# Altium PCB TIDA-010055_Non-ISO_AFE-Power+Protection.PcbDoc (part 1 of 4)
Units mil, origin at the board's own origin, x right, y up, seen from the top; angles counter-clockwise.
Board outline 3622.05 x 4330.71 mil, 4 copper layers (Top Layer, GND Layer, PWR Layer, Bottom Layer), stack 63.6 mil thick; 398 components, 177 nets, 1104 pads, 428 vias.
Unrouted connection lines stored in the file: 1.
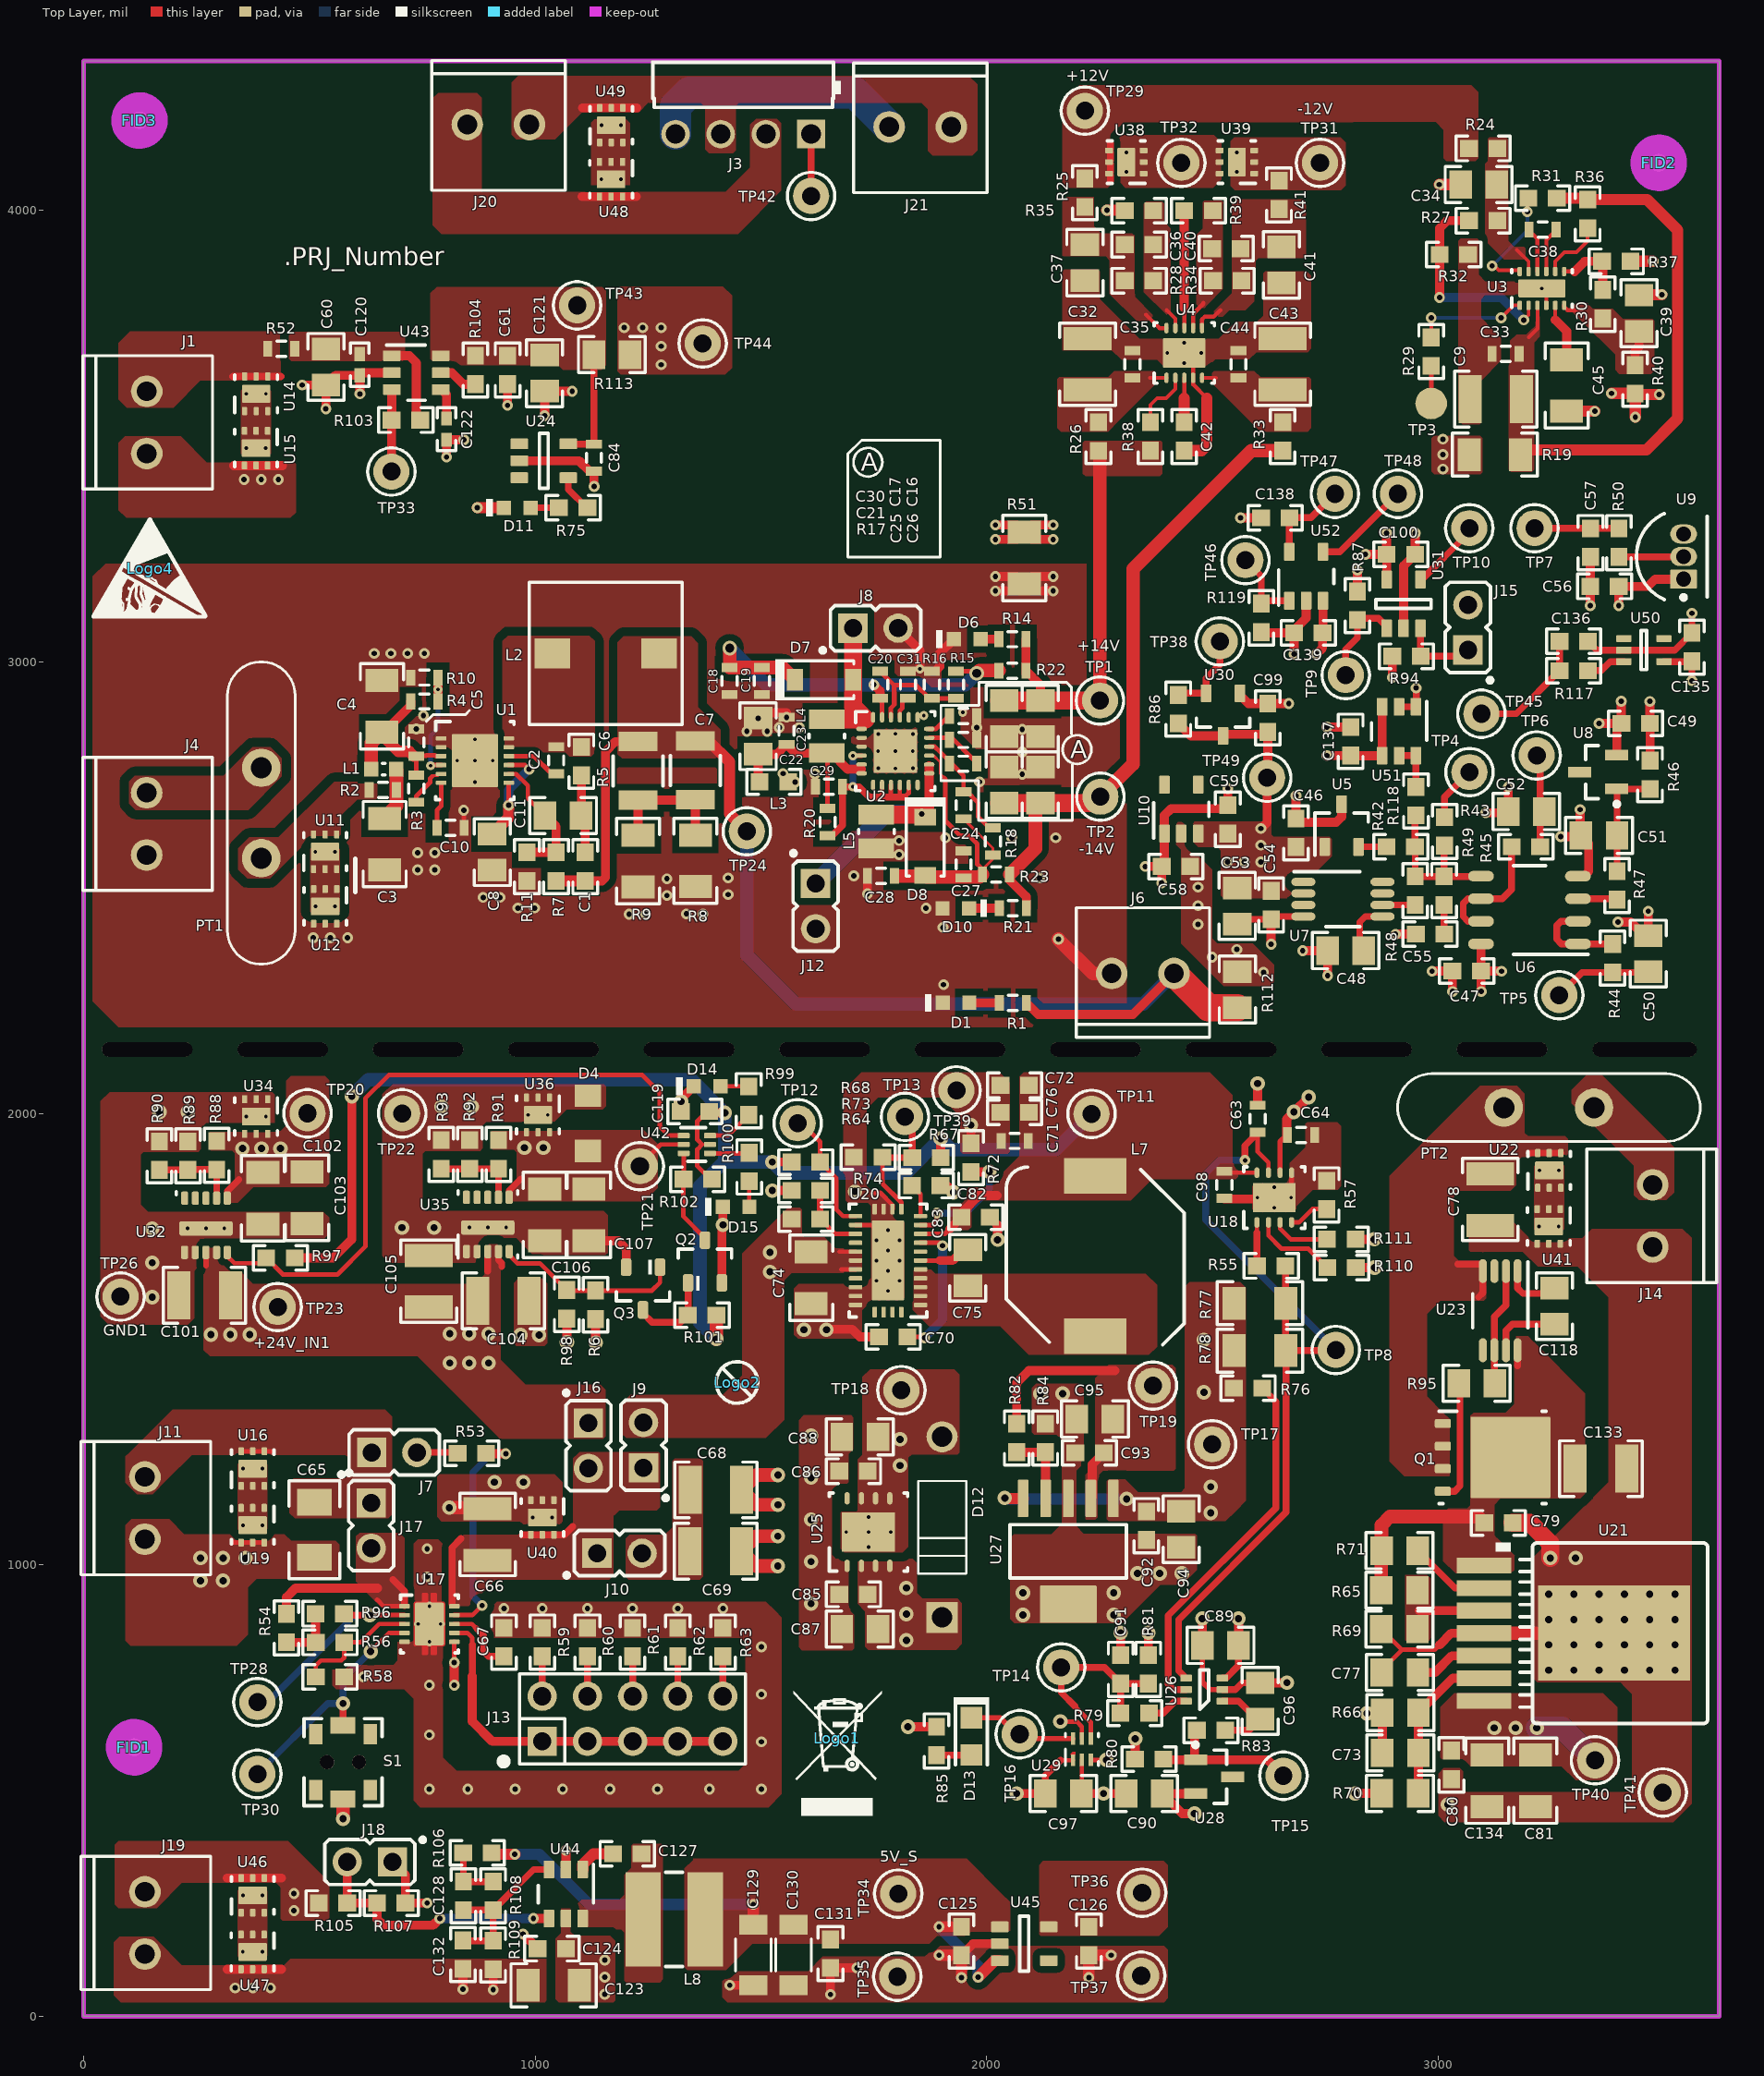
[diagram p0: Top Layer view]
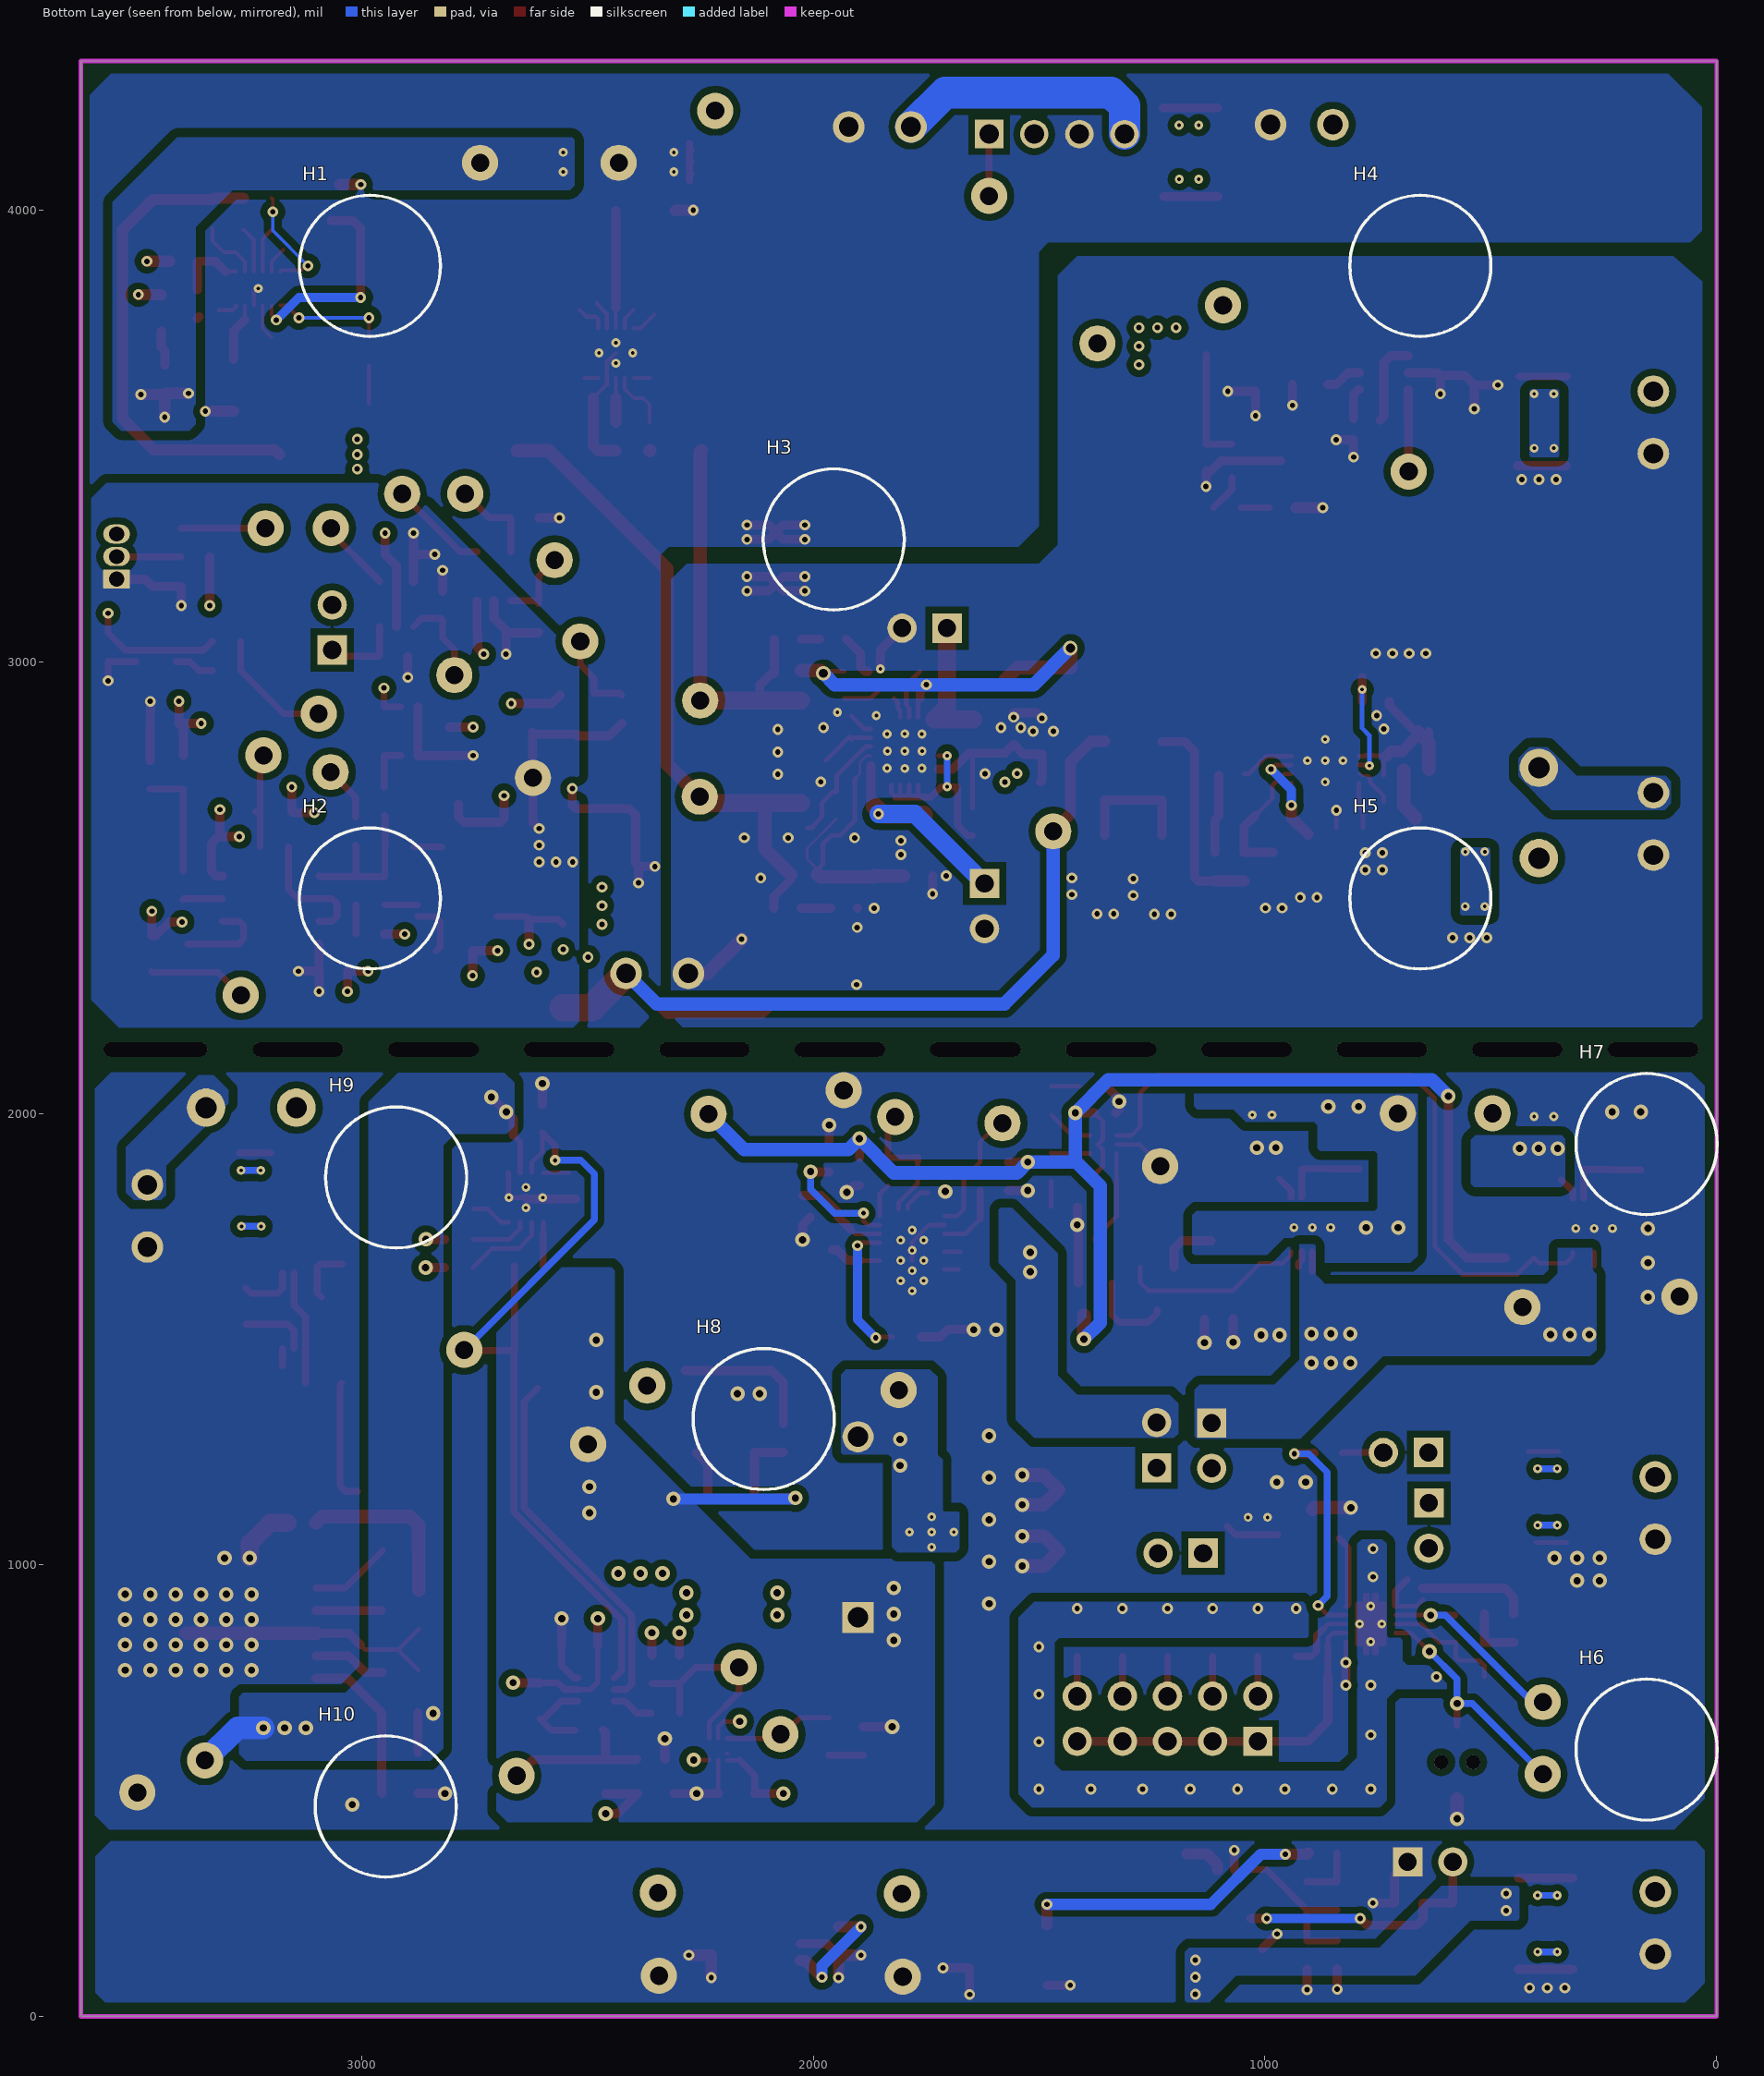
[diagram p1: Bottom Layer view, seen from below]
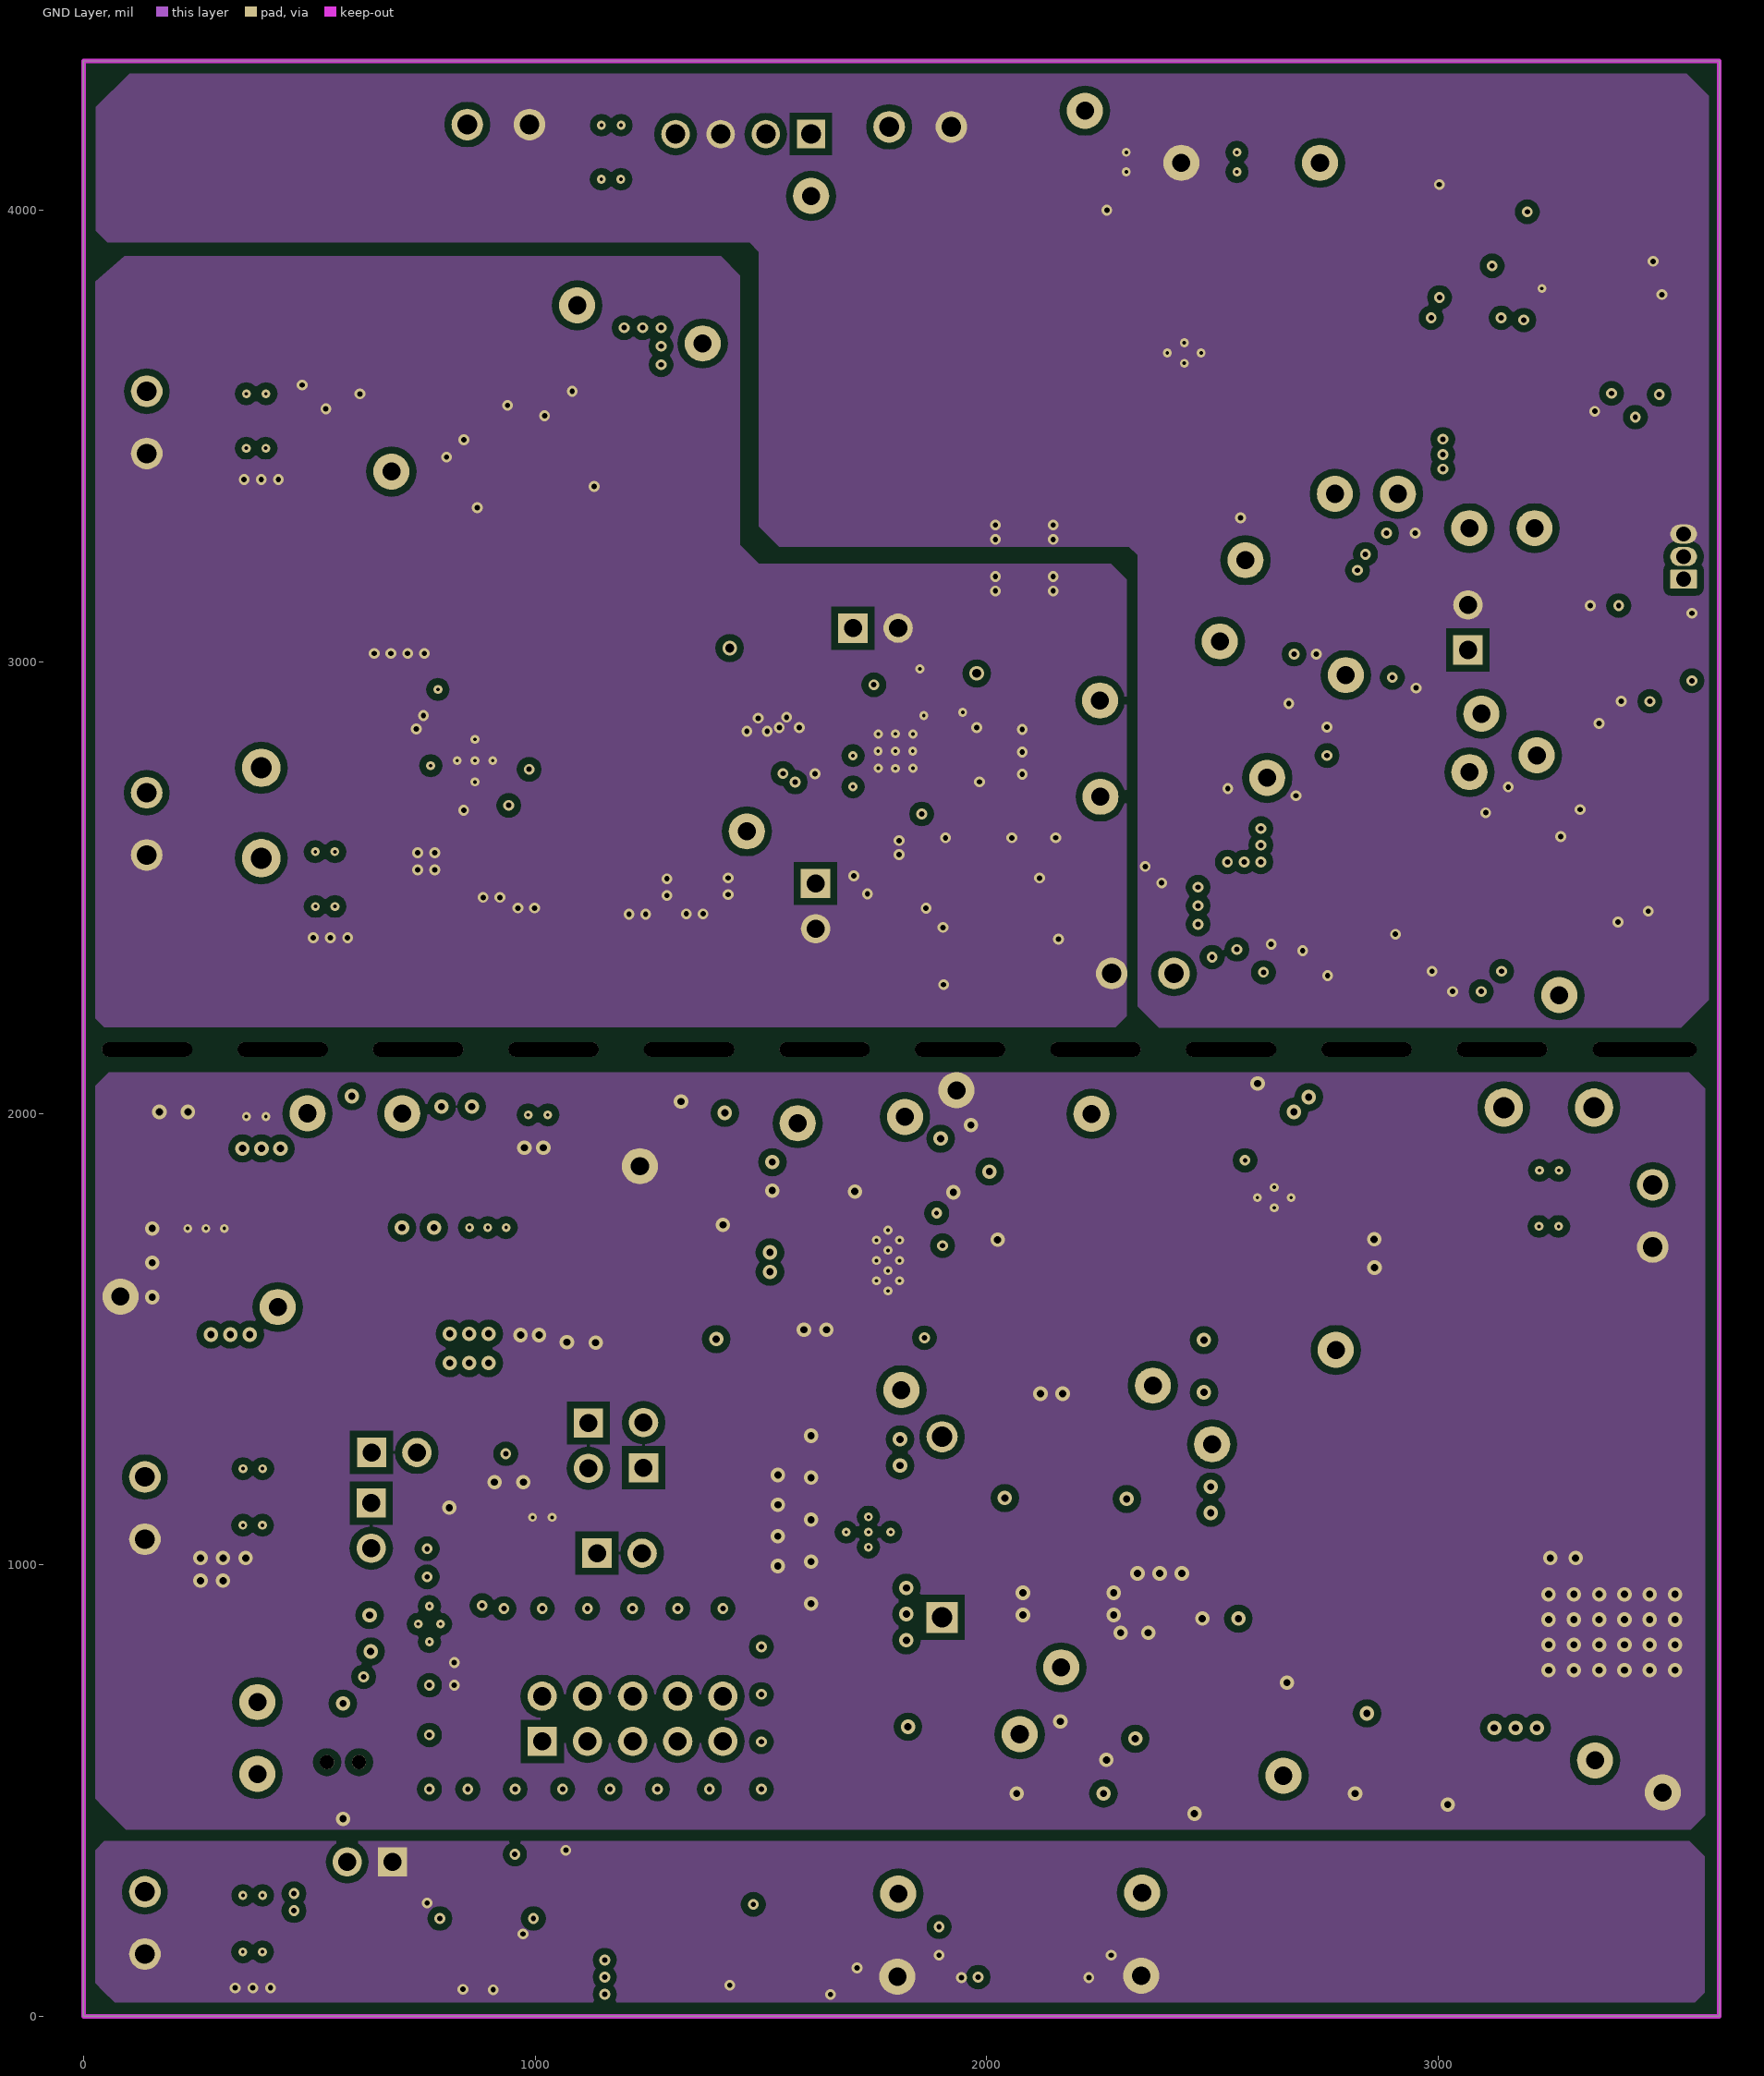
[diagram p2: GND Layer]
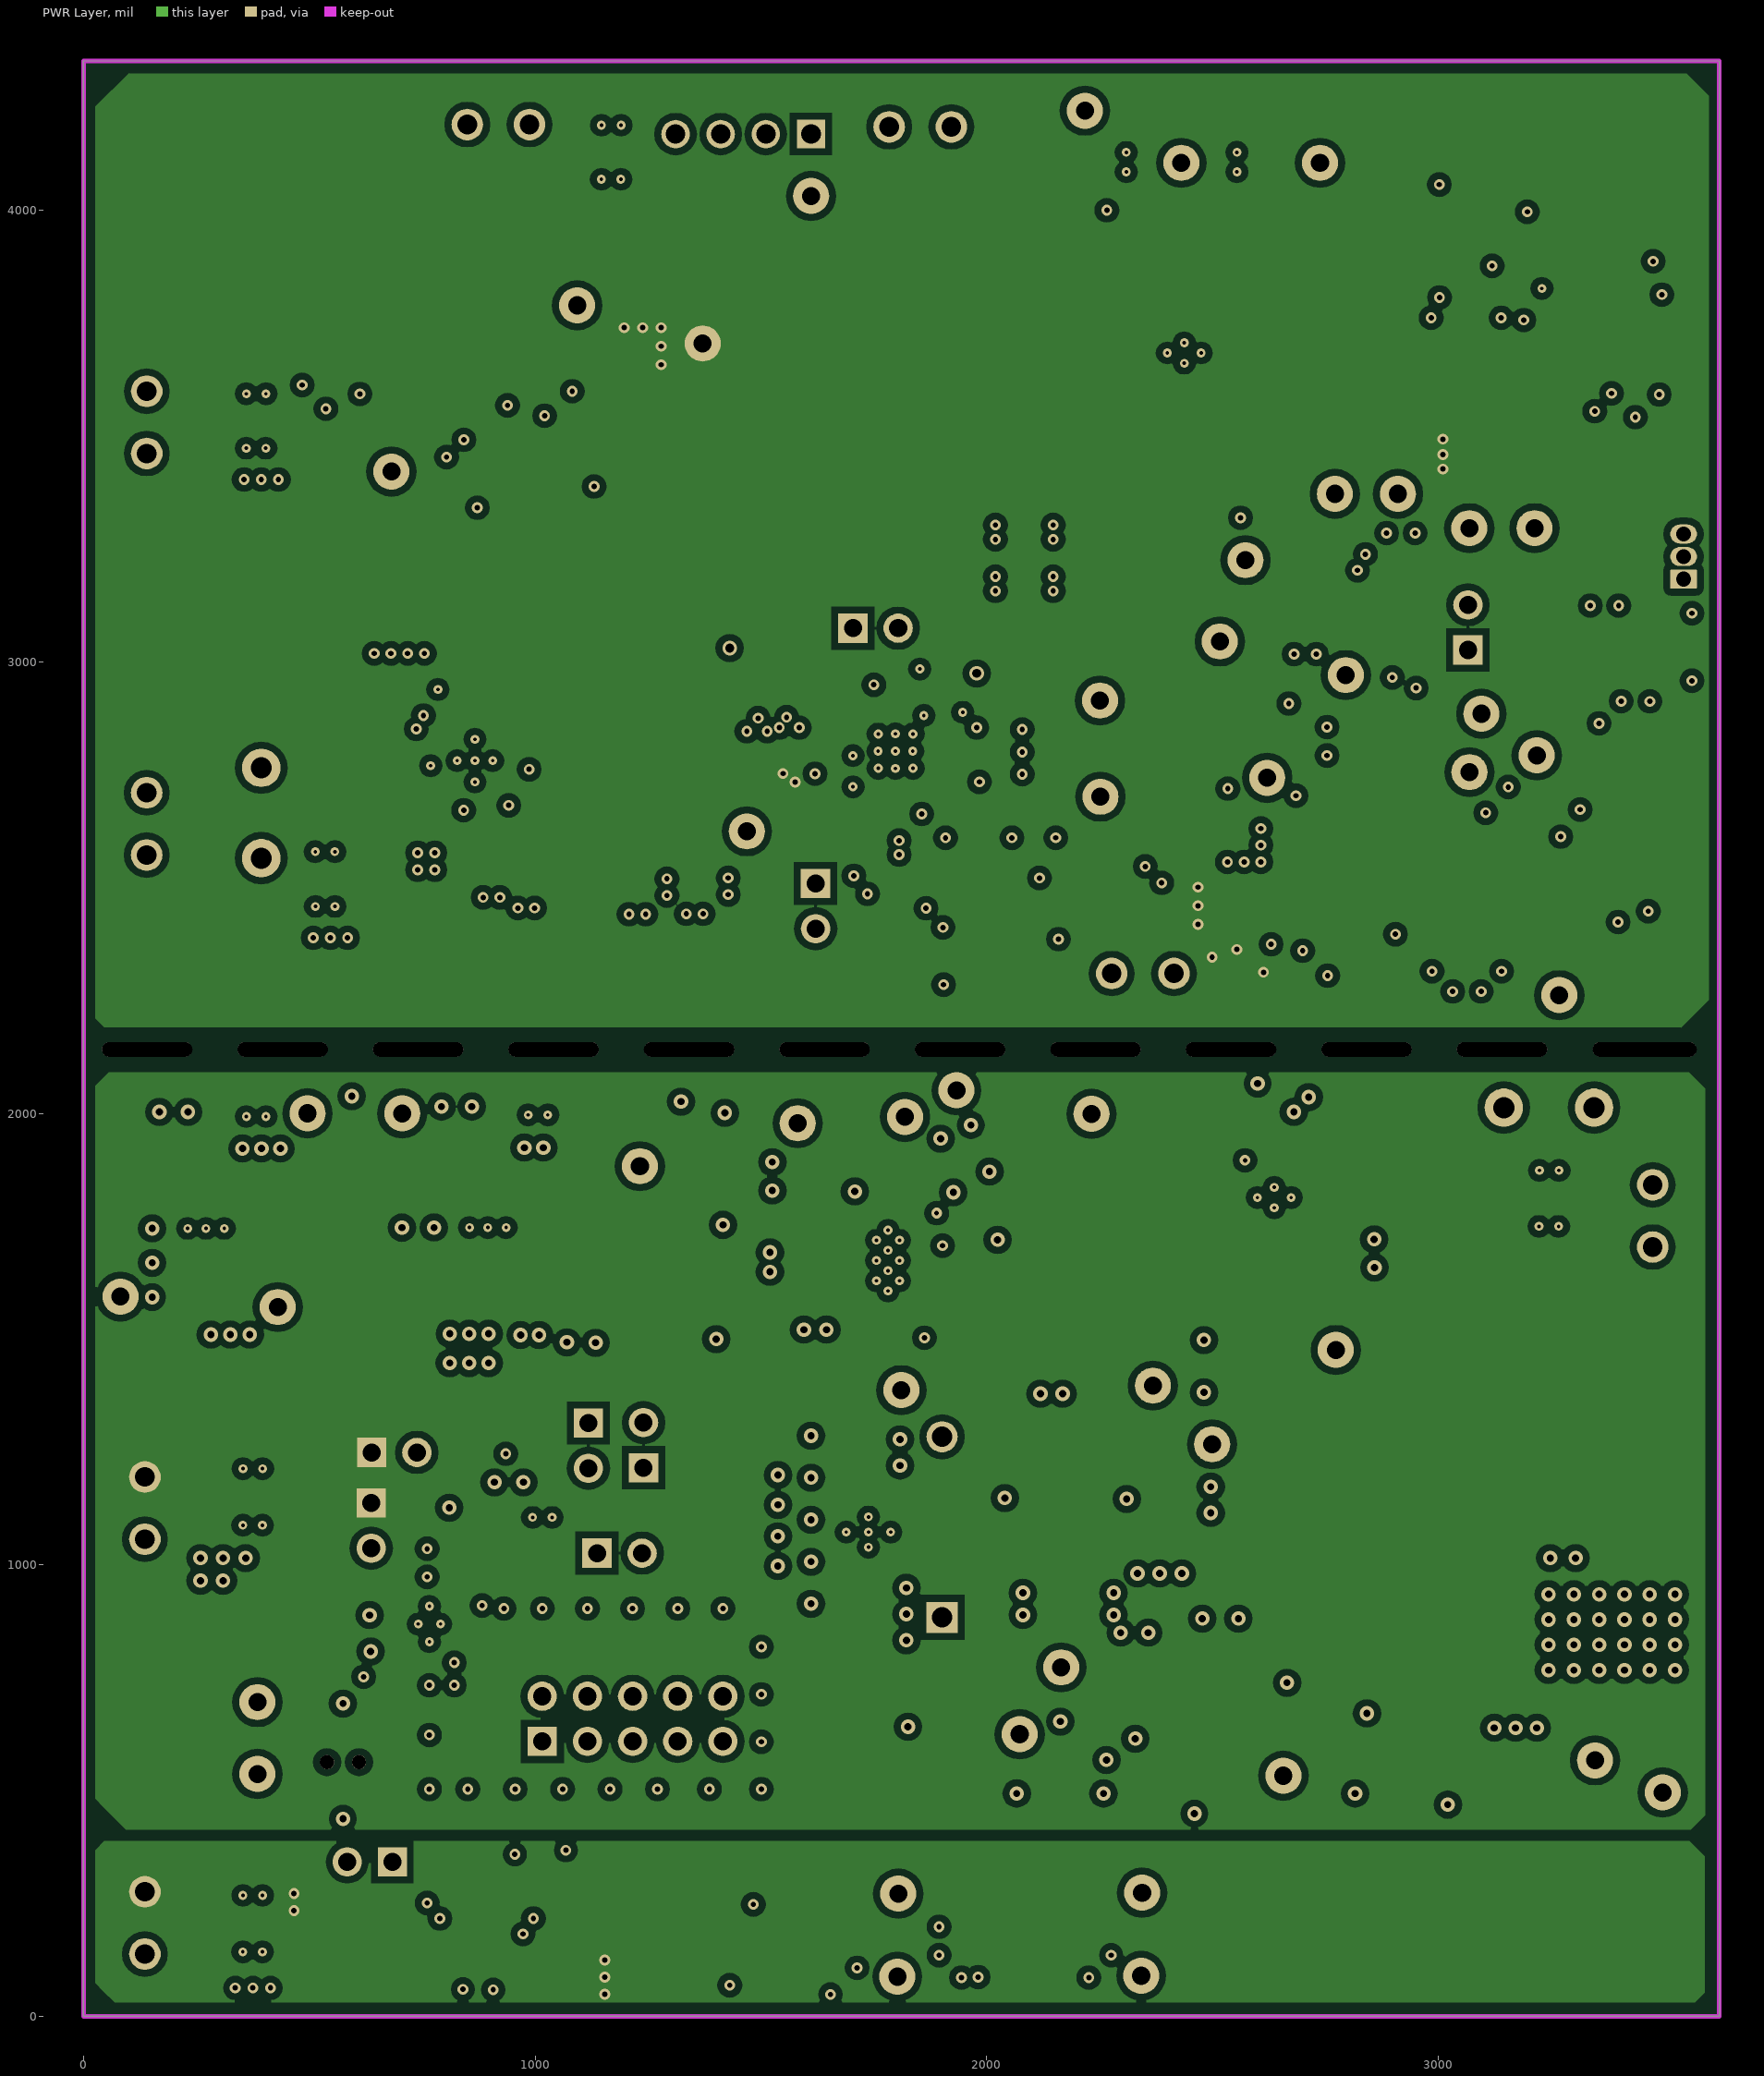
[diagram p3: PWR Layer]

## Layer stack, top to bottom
Top Solder: solder mask 0.3, Solder Resist, Dk 3.5
Top Layer: signal copper 1.4
Dielectric1: core 15, FR-4 High Tg, Dk 4.5
GND Layer: signal copper 1.4
Dielectric 2: prepreg 28, FR-4 High Tg, Dk 4.5
PWR Layer: signal copper 1.4
Dielectric 3: core 15, FR-4 High Tg, Dk 4.5
Bottom Layer: signal copper 1.4
Bottom Solder: solder mask 0.3, Solder Resist, Dk 3.5

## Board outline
0,0 0,4330.71 3622.05,4330.64 3622.05,0

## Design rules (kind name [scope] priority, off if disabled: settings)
AcuteAngle [All] p1: minimum=4.50000000000000E+0001 checktracksonly=FALSE
AssemblyTestPointUsage [All] p1: valid=2
BoardOutlineClearance BoardOutlineClearance_MountingHoles [OnCopper and InComponentClass('Mounting Holes')] p1: gap=30 ignorepadtopadclearanceinfootprint=FALSE
BoardOutlineClearance BoardOutlineClearance_Poly [OnCopper and InPoly] p2: gap=25 ignorepadtopadclearanceinfootprint=FALSE
BoardOutlineClearance [OnCopper and Not InComponentClass('Logo') and not InComponentClass('FiducialMark') and not InRegion(1000,500,4000,800)] p3: gap=15 ignorepadtopadclearanceinfootprint=FALSE
Clearance Clearance_Poly_poly [InPoly vs InPoly] p1: gap=20 ignorepadtopadclearanceinfootprint=FALSE except(0: Arc-Hole Track-Hole SMDPad-Hole THPad-Hole Via-Hole Fill-Hole Poly-Hole Region-Hole Text-Hole)
Clearance Clearance_Keepouts [((IsTrack Or IsArc) And Not InPoly) And IsFree and IsKeepOut vs ((IsTrack Or IsArc) And Not InPoly) And IsFree and IsKeepOut] p2: gap=20 ignorepadtopadclearanceinfootprint=FALSE except(0: Arc-Hole Track-Hole SMDPad-Hole THPad-Hole Via-Hole Fill-Hole Poly-Hole Region-Hole Text-Hole)
Clearance Clearance_Poly [InPolygon] p3: gap=15 ignorepadtopadclearanceinfootprint=FALSE except(0: Arc-Hole Track-Hole SMDPad-Hole THPad-Hole Via-Hole Fill-Hole Poly-Hole Region-Hole Text-Hole)
Clearance [All] p4: gap=7.87 ignorepadtopadclearanceinfootprint=FALSE except(0: Arc-SMDPad Arc-THPad Arc-Hole Track-Hole SMDPad-Hole THPad-Hole Via-Hole Fill-Hole Poly-Hole Region-Hole Text-Hole)
ComponentClearance ComponentClearance_MountingHoles_FiducialMarks [InComponentClass('Mounting Holes') vs InComponentClass('FiducialMark')] p1: gap=10 collisioncheckmode=3 verticalgap=10 showdistances=FALSE
ComponentClearance ComponentClearance_Shunt [InComponentClass('Header') vs InComponentClass('Shunt')] p2: gap=0 collisioncheckmode=3 verticalgap=0 showdistances=FALSE
ComponentClearance ComponentClearance_Logo [InComponentClass('Logo')] p3: gap=5 collisioncheckmode=3 verticalgap=5 showdistances=FALSE
ComponentClearance ComponentClearance_ScrewToNut [(HasFootprint('NY PMS 440 0025 PH')) vs (HasFootprint('Keystone_1902C'))] p4: gap=5 collisioncheckmode=3 verticalgap=10 showdistances=FALSE
ComponentClearance ComponentClearance_MountingHoles [InComponentClass('Mounting Holes')] p5: gap=250 collisioncheckmode=3 verticalgap=100000 showdistances=FALSE
ComponentClearance ComponentClearance_SmallPassives [HasFootprint('0201*') or HasFootprint('0402*') or HasFootprint('0508') or HasFootprint('0603*') or HasFootprint('0612') or HasFootprint('0805*') or HasFootprint('0815*') or HasFootprint('0830*') or HasFootprint('1206*') or HasFootprint('1210*') or HasFootprint('1808*') or HasFootprint('1812*') or HasFootprint('1825*') or HasFootprint('2010*') or HasFootprint('2220*') or HasFootprint('2225*') or HasFootprint('2512*') or HasFootprint('2728*') or HasFootprint('3518*') vs HasFootprint('0201*') or HasFootprint('0402*') or HasFootprint('0508') or HasFootprint('0603*') or HasFootprint('0612') or HasFootprint('0805*') or HasFootprint('0815*') or HasFootprint('0830*') or HasFootprint('1206*') or HasFootprint('1210*') or HasFootprint('1808*') or HasFootprint('1812*') or HasFootprint('1825*') or HasFootprint('2010*') or HasFootprint('2220*') or HasFootprint('2225*') or HasFootprint('2512*') or HasFootprint('2728*') or HasFootprint('3518*')] p6: gap=5 collisioncheckmode=3 verticalgap=5 showdistances=FALSE
ComponentClearance ComponentClearance_THtoSMT [IsThruComponent vs IsSMTComponent] p7: gap=5 collisioncheckmode=3 verticalgap=5 showdistances=FALSE
ComponentClearance ComponentClearance_THtoTH [IsThruComponent vs IsThruComponent] p8: gap=0 collisioncheckmode=3 verticalgap=10 showdistances=FALSE
ComponentClearance [All] p9: gap=10 collisioncheckmode=3 verticalgap=10 showdistances=FALSE
DiffPairsRouting [All] p1: maxlimit=100 minlimit=10 mostfreqgap=10 toplayer_minwidth=15 toplayer_maxwidth=15 toplayer_prefwidth=15 midlayer1_minwidth=15 midlayer1_maxwidth=15 midlayer1_prefwidth=15 midlayer2_minwidth=15 midlayer2_maxwidth=15 midlayer2_prefwidth=15 bottomlayer_minwidth=15 bottomlayer_maxwidth=15 bottomlayer_prefwidth=15 maxuncoupledlength=1000
FabricationTestPointUsage TestPointUsage [All] p1: valid=2 allowmultiple=FALSE
FabricationTestpoint Testpoint [All] p1: side=3 testpointundercomponent=TRUE minsize=40 maxsize=100 preferedsize=60 minholesize=0 maxholesize=40 preferedholesize=32 testpointgrid=1 allowsidetop=TRUE allowsidebottom=TRUE usegrid=TRUE gridtolerance=0.01
FanoutControl Fanout_LCC [IsLCC] p1: bgadir=Out bgaviamode=Centered fanoutstyle=Auto fanoutdirection=Alternating viagrid=1 // Fanout_LCC (Default Rule)
FanoutControl Fanout_BGA [IsBGA] p2: bgadir=Out bgaviamode=Centered fanoutstyle=Auto fanoutdirection=Alternating viagrid=1 // Fanout_BGA (Default Rule)
FanoutControl Fanout_Default [All] p4: bgadir=Out bgaviamode=Centered fanoutstyle=Auto fanoutdirection=Alternating viagrid=1 // Fanout_Default (Default Rule)
FanoutControl Fanout_Small [(CompPinCount < 5)] p5: bgadir=Out bgaviamode=Centered fanoutstyle=Auto fanoutdirection=OutThenIn viagrid=1 // Fanout_Small (Default Rule)
HoleSize [All] p1: absolutevalues=TRUE maxlimit=251 minlimit=7.87 maxpercent=80.000 minpercent=20.000
MinimumAnnularRing MinimumAnnularRing_ThermalPadVias [IsVia and InAnyComponent] p1: minimumring=4
MinimumAnnularRing [All] p2: minimumring=4
MinimumSolderMaskSliver MinimumSolderMaskSliver_Logo [InComponentClass('Logo') vs InComponentClass('Logo')] p1: minsoldermaskwidth=0.7
MinimumSolderMaskSliver [All] p2: minsoldermaskwidth=3.94
PlaneClearance [All] p1: clearance=10
PlaneConnect [All] p1: planeconnectstyle=Relief reliefexpansion=10 reliefentries=4 reliefconductorwidth=10 reliefairgap=10
PolygonConnect PolygonConnectThermalVia [isvia] p1: connectstyle=Direct reliefconductorwidth=10 reliefentries=4 polygonreliefangle="90 Angle" airgapwidth=10
PolygonConnect PolygonConnectThermalPad [((ObjectKind = 'Pad') And (((Name Like 'U*') or (Name Like 'D*')) and (InComponentClass('TIDA-00183_pg-4_Driver') or InComponentClass('TIDA-00183_pg-5_OP_Connector')))) or ((ObjectKind = 'Pad') And (Name like 'U61*'))] p2: connectstyle=Direct reliefconductorwidth=10 reliefentries=4 polygonreliefangle="90 Angle" airgapwidth=10
PolygonConnect [All] p3: connectstyle=Direct reliefconductorwidth=10 reliefentries=4 polygonreliefangle="90 Angle" airgapwidth=5
RoutingVias ThermalPadVias [IsVia and InAnyComponent] p1: holewidth=7.87 width=19.68 viastyle="Through Hole" minholewidth=7.87 minwidth=19.68 maxholewidth=12.99 maxwidth=23.62
RoutingVias [All] p2: holewidth=16 width=34 viastyle="Through Hole" minholewidth=8 minwidth=20 maxholewidth=40 maxwidth=65
SilkToBoardRegionClearance [Not ((IsComment or IsDesignator) And (Hide <> 'False')) and not InRegion(1000,500,4000,800)] p1:
SilkToSilkClearance SilkToSilkClearance_Pb-FreeLogo [(HasFootprint('Pb-Free_Overlay_Medium') OR HasFootprint('Pb-Free_Overlay_Small')) vs (HasFootprint('Pb-Free_Overlay_Medium') OR HasFootprint('Pb-Free_Overlay_Small'))] p1: silktosilkclearance=0
SilkToSilkClearance [All] p2: silktosilkclearance=4
SilkToSolderMaskClearance SilkToComponentPadClearance [IsPad and InAnycomponent] p1: minsilkscreentomaskgap=5 clearancetoexposedcopper=TRUE
SilkToSolderMaskClearance "Silk to Solder Mask Opening" [All] p2: minsilkscreentomaskgap=4 clearancetoexposedcopper=FALSE
SolderMaskExpansion [All] p1: expansion=1.97
Width [All] p1: maxlimit=100 minlimit=6 preferedwidth=10 checkconnectedcopper=TRUE
14 further rules are at their usual default settings.

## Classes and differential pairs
component class "TIDA-010055_Non-ISO_AFE-Power+Protection _Pg3": C1 C2 C3 C4 C5 C6 C7 C8 C10 C11 C60 C61 C84 C120 C121 C122 D1 D11 J1 J4 J6 L1 L2 PT1 R1 R2 R3 R4 R5 R7 R8 R9 R10 R11 R52 R75 R103 R104 R112 R113 TP24 TP33 TP43 TP44 U1 U11 U12 U14 U15 U24 U43
component class "TIDA-010055_Non-ISO_AFE-Power+Protection _Pg8": C123 C124 C125 C126 C127 C128 C129 C130 C131 C132 J3 J18 J19 J20 J21 L8 R105 R106 R107 R108 R109 TP34 TP35 TP36 TP37 TP42 U44 U45 U46 U47 U48 U49
component class "TIDA-010055_Non-ISO_AFE-Power+Protection _Pg7": C63 C64 C73 C77 C78 C79 C80 C81 C85 C86 C87 C88 C89 C90 C91 C92 C93 C94 C95 C96 C97 C98 C118 C133 C134 D12 D13 J14 PT2 Q1 R55 R57 R65 R66 R69 R70 R71 R76 R77 R78 R79 R80 R81 R82 R83 R84 R85 R95 R110 R111 TP8 TP14 TP15 TP16 TP17 TP18 TP19 TP40 TP41 U18 U21 U22 U23 U25 U26 U27 U28 U29 U41
component class "TIDA-010055_Non-ISO_AFE-Power+Protection _Pg5": C9 C32 C33 C34 C35 C36 C37 C38 C39 C40 C41 C42 C43 C44 C45 C46 C47 C48 C49 C50 C51 C52 C53 C54 C55 C56 C57 C58 C59 C99 C100 C135 C136 C137 C138 C139 J15 R19 R24 R25 R26 R27 R28 R29 R30 R31 R32 R33 R34 R35 R36 R37 R38 R39 R40 R41 R42 R43 R44 R45 R46 R47 R48 R49 R50 R51 R86 R87 R94 R117 R118 R119 TP3 TP4 TP5 TP6 TP7 TP9 TP10 TP29 TP31 TP32 TP38 TP45 TP46 TP47 TP48 TP49 U3 U4 U5 U6 U7 U8 U9 U10 U30 U31 U38 U39 U50 U51 U52
component class Header: J3 J7 J8 J9 J10 J12 J13 J15 J16 J17 J18
component class AssemblyNote: ZZ1 ZZ2 ZZ3 ZZ4
component class FiducialMark: FID1 FID2 FID3
component class "TIDA-010055_Non-ISO_AFE-Power+Protection _EVM_Hardware_Pg9": FID1 FID2 FID3 H1 H2 H3 H4 H5 H6 H7 H8 H9 H10 Logo1 Logo2 Logo3 Logo4 ZZ1 ZZ2 ZZ3 ZZ4
component class "TIDA-010055_Non-ISO_AFE-Power+Protection _Pg4": C16 C17 C18 C19 C20 C21 C22 C23 C24 C25 C26 C27 C28 C29 C30 C31 D6 D7 D8 D10 J8 J12 L3 L4 L5 R14 R15 R16 R17 R18 R20 R21 R22 R23 TP1 TP2 U2
component class "TIDA-010055_Non-ISO_AFE-Power+Protection _Pg6": C65 C66 C67 C68 C69 C70 C71 C72 C74 C75 C76 C82 C83 C101 C102 C103 C104 C105 C106 C107 C119 D4 D14 D15 J7 J9 J10 J11 J13 J16 J17 L7 Q2 Q3 R6 R53 R54 R56 R58 R59 R60 R61 R62 R63 R64 R67 R68 R72 R73 R74 R88 R89 R90 R91 R92 R93 R96 R97 R98 R99 R100 R101 R102 S1 TP11 TP12 TP13 TP20 TP21 TP22 TP23 TP26 TP28 TP30 TP39 U16 U17 U19 U20 U32 U34 U35 U36 U40 U42

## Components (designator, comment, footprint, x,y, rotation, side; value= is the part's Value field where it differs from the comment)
C1 "06031C472KAT2A" 0603 1110.88,2546.43 r90 top value=4700pF
C2 "CGA3E2X7R1H103K080AA" 0603S 1046.54,2781.94 r90 top value=0.01uF
C3 "UMK316B7225KL-T" 1206 666.73,2596.16 r270 top value=2.2uF
C4 "UMK316B7225KL-T" 1206 660.73,2901.16 r90 top value=2.2uF
C5 "C0603X124K5RAC7867" 0603S 736.73,2821.16 r90 top value=0.1uF
C6 "C1210C107M8PACTU" 1210_280 1227.88,2758.39 r270 top value=100uF
C7 "C1210C107M8PACTU" 1210_280 1354.88,2759.39 r270 top value=100uF
C8 "C0805C104K1RACTU" 0805_HV 904.88,2578.43 r270 top value=0.1uF
C9 "" 1210 3127.11,3581.98 r0 top value=10uF
C10 "885012206034" 0603S 812.73,2632.16 r0 top value=1000pF
C11 "C0805C104K1RACTU" 0805_HV 1061.88,2659.43 r180 top value=0.1uF
C16 "GRM21BC71E106KE11L" 0805_HV 2118.73,2874.16 r270 top value=10uF
C17 "GRM21BC71E106KE11L" 0805_HV 2038.73,2874.16 r270 top value=10uF
C18 "CGA3E1X7R1E105K080AC" 0603S 1430.73,2957.43 r270 top value=1uF
C19 "C0603X124K5RAC7867" 0603S 1501.88,2957.43 r270 top value=0.1uF
C20 "06035A6R8CAT2A" 0603S 1763.73,2949.16 r90 top value=6.8pF
C21 "EMK107B7224KA-T" 0603S 1947.73,2827.16 r0 top value=0.22uF
C22 "GRM21BC71E106KE11L" 0805_HV 1493.73,2835.16 r90 top value=10uF
C23 "C0603X124K5RAC7867" 0603S 1556.73,2847.16 r90 top value=0.1uF
C24 "C0603C569K5GACTU" 0603S 1948.73,2682.16 r270 top value=5.6pF
C25 "GRM21BC71E106KE11L" 0805_HV 2038.73,2727.16 r270 top value=10uF
C26 "GRM21BC71E106KE11L" 0805_HV 2118.73,2727.16 r270 top value=10uF
C27 "CGA3E1X7R1E105K080AC" 0603S 1948.73,2551.16 r270 top value=1uF
C28 "C0603X124K5RAC7867" 0603S 1765.73,2526.16 r0 top value=0.1uF
C29 "C0603X124K5RAC7867" 0603S 1650.73,2723.16 r180 top value=0.1uF
C30 "885012206087" 0603S 1947.73,2880.16 r0 top value=4700pF
C31 "885012206040" 0603S 1825.73,2949.16 r90 top value=0.01uF
C32 "" 1210 2223.4,3658.91 r270 top value=10uF
C33 "CGA3E1X7R1E105K080AC" 0603S 3149.2,3681.98 r180 top value=1uF
C34 "C0805C225K8RACTU" 0805_HV 3089.2,4056.98 r180 top value=2.2uF
C35 "CGA3E1X7R1E105K080AC" 0603S 2322.4,3659 r90 top value=1uF
C36 "885012206040" 0603 2337.4,3923.93 r0 top value=0.01uF
C37 "C0805C225K8RACTU" 0805_HV 2217.4,3884 r270 top value=2.2uF
C38 "CGA3E1X7R1E105K080AC" 0603S 3230.7,3956.98 r180 top value=1uF
C39 "C0805C225K8RACTU" 0805_HV 3444.2,3771.98 r90 top value=2.2uF
C40 "885012206040" 0603 2530.4,3915 r180 top value=0.01uF
C41 "C0805C225K8RACTU" 0805_HV 2652.4,3879 r270 top value=2.2uF
C42 "885012206040" 0603 2437.4,3499 r270 top value=0.01uF
C43 "" 1210 2655.4,3658.91 r270 top value=10uF
C44 "CGA3E1X7R1E105K080AC" 0603S 2557.4,3659 r90 top value=1uF
C45 "C3216X7R1E475M160AC" 1206 3284.2,3611.98 r270 top value=4.7uF
C46 "06033D104KAT2A" 0603 2684.81,2621.23 r90 top value=0.1uF
C47 "06033D104KAT2A" 0603 3062.81,2315.23 r0 top value=0.1uF
C48 "CL21B105KPFNNNE" 0805_HV 2794.81,2360.23 r180 top value=1uF
C49 "06033D104KAT2A" 0603 3436.85,2863.72 r0 top value=0.1uF
C50 "C2012X7R1H105K125AE" 0805_HV 3464.85,2353.72 r90 top value=1uF
C51 "C2012X7R1H105K125AE" 0805_HV 3355.81,2615.23 r180 top value=1uF
C52 "C2012X7R1H105K125AE" 0805_HV 3194.81,2668.23 r180 top value=1uF
C53 "CL21B105KPFNNNE" 0805_HV 2554.81,2459.23 r270 top value=1uF
C54 "06033D104KAT2A" 0603 2629.81,2461.23 r270 top value=0.1uF
C55 "EMK107BBJ106MA-T" 0603 2981.81,2397.23 r180 top value=10uF
C56 "06033D104KAT2A" 0603 3368,3167 r0 top value=0.1uF
C57 "06033D104KAT2A" 0603 3337,3264 r90 top value=0.1uF
C58 "06033D104KAT2A" 0603 2418.87,2546.7 r180 top value=0.1uF
C59 "CGB3B3X7R0J105K055AB" 0603 2533.87,2651.2 r90 top value=1uF
C60 "C2012X5R1E106K085AC" 0805_HV 536.66,3652.97 r270 top value=10uF
C61 "06033D104KAT2A" 0603 938.99,3646.25 r270 top value=0.1uF
C63 "CGA3E1X7R1E105K080AC" 0603S 2600,1988 r90 top value=1uF
C64 "CGA3E1X7R1E105K080AC" 0603S 2696,1952 r0 top value=1uF
C65 "C3216X7R2A105K160AA" 1206_180M 511.12,1077.89 r270 top value=1uF
C66 "C3225X7R2A225K230AB" 1210_270 894.84,1067.11 r90 top value=2.2uF
C67 "C0603C223K4RACTU" 0603 930.84,828.96 r90 top value=0.022uF
C68 "C3225X7S1H106M250AB" 1210_270 1400.12,1165.89 r0 top value=10uF
C69 "C3225X7S1H106M250AB" 1210_270 1399.84,1030.36 r0 top value=10uF
C70 "C0603X124K5RAC7867" 0603 1793,1505 r0 top value=0.1uF
C71 "CGA3E1X7R1E105K080AC" 0603S 2062,1939 r180 top value=1uF
C72 "EMK107BBJ106MA-T" 0603 2062,2062 r180 top value=10uF
C73 "08051C223JAT2A" 0805_HV 2915.86,583.68 r0 top value=0.022uF
C74 "C3216X7S2A225K160AB" 1206 1611.43,1635.99 r270 top value=2.2uF
C75 "GCM21BR71H474KA55L" 0805_HV 1958.12,1657.89 r270 top value=0.47uF
C76 "EMK107BBJ106MA-T" 0603 2062,2002 r180 top value=10uF
C77 "08051C223JAT2A" 0805_HV 2914.86,761.68 r180 top value=0.022uF
C78 "C3225X7S1H106M250AB" 1210_270 3115,1809 r270 top value=10uF
C79 "UMK107BJ105KA-T" 0603 3133,1093 r0 top value=1uF
C80 "UMK107BJ105KA-T" 0603 3029,557 r270 top value=1uF
C81 "EMK316BBJ476ML-T" 1206 3215,522 r270 top value=47uF
C82 "GRM1885C1H222JA01D" 0603 1866,1840 r0 top value=2200pF
C83 "UMK107BJ105KA-T" 0603 1975.62,1769.89 r180 top value=1uF
C84 "C0603X124K5RAC7867" 0603S 1130.18,3452.2 r270 top value=0.1uF
C85 "06031A101GAT2A" 0603 1705.12,934.6 r0 top value=100pF
C86 "06031A101GAT2A" 0603 1705.12,1207.6 r0 top value=100pF
C87 "C2012X5R1E106K085AC" 0805_HV 1719.12,857.6 r0 top value=10uF
C88 "C2012X5R1E106K085AC" 0805_HV 1719.12,1283.6 r0 top value=10uF
C89 "CMP-0007886-2" 0805_HV 2517.68,821.64 r0 top value=0.1uF
C90 "CMP-0007886-2" 0805_HV 2348.68,493.64 r180 top value=0.1uF
C91 "0603ZC103KAT2A" 0603 2296.68,768.64 r90 top value=0.01uF
C92 "06031A101GAT2A" 0603 2353.54,1086.89 r90 top value=100pF
C93 "06031A101GAT2A" 0603 2227.54,1247.89 r0 top value=100pF
C94 "C2012X5R1E106K085AC" 0805_HV 2430.54,1078.89 r90 top value=10uF
C95 "C2012X5R1E106K085AC" 0805_HV 2239.54,1322.89 r0 top value=10uF
C96 "CMP-0007886-2" 0805_HV 2605.68,698.64 r270 top value=0.1uF
C97 "CMP-0007886-2" 0805_HV 2169.68,493.64 r0 top value=0.1uF
C98 "CGA3E1X7R1E105K080AC" 0603S 2525.99,1841.76 r270 top value=1uF
C99 "06033D104KAT2A" 0603 2622.25,2876 r90 top value=0.1uF
C100 "06033D104KAT2A" 0603 2917,3238.2 r0 top value=0.1uF
C101 "C3225X7S1H106M250AB" 1210_270 268,1597 r180 top value=10uF
C102 "EMK316BBJ476ML-T" 1206 397.11,1812 r270 top value=47uF
C103 "EMK316BBJ476ML-T" 1206 495,1813 r270 top value=47uF
C104 "C3225X7S1H106M250AB" 1210_270 929.75,1584.94 r0 top value=10uF
C105 "C3225X7S1H106M250AB" 1210_270 764.2,1627.98 r90 top value=10uF
C106 "EMK316BBJ476ML-T" 1206 1021.2,1774.86 r270 top value=47uF
C107 "EMK316BBJ476ML-T" 1206 1119.09,1774.86 r270 top value=47uF
C118 "0805YC224KAT2A" 0805_HV 3257,1573 r90 top value=0.22uF
C119 "06033D104KAT2A" 0603 1354,2004 r180 top value=0.1uF
C120 "CGA2B2C0G1H102J050BA" 0402 611.81,3658.25 r270 top value=1000pF
C121 "C2012X5R1E106K085AC" 0805_HV 1020.99,3639.25 r270 top value=10uF
C122 "CGA2B2C0G1H102J050BA" 0402 803.81,3515.25 r270 top value=1000pF
C123 "UMK316B7225KL-T" 1206 1041.07,68.98 r180 top value=2.2uF
C124 "C0603X124K5RAC7867" 0603 1037.07,149.98 r180 top value=0.1uF
C125 "UMK107BJ105KA-T" 0603 1944.07,166.98 r270 top value=1uF
C126 "UMK107BJ105KA-T" 0603 2226.07,166.98 r270 top value=1uF
C127 "C0603X124K5RAC7867" 0603 1204.07,359.98 r0 top value=0.1uF
C128 "06035A220JAT2A" 0603 841.07,266.98 r270 top value=22pF
C129 "CL31B226MPHNNNE" 1206_180 1483.07,135.98 r270 top value=22uF
C130 "CL31B226MPHNNNE" 1206_180 1572.07,135.98 r270 top value=22uF
C131 "C0603X124K5RAC7867" 0603 1654.07,138.98 r90 top value=0.1uF
C132 "06035A220JAT2A" 0603 840.07,136.98 r270 top value=22pF
C133 "C3225X7S1H106M250AB" 1210_270 3360,1213 r0 top value=10uF
C134 "EMK316BBJ476ML-T" 1206 3108,522 r270 top value=47uF
C135 "06033D104KAT2A" 0603 3561.61,3032.58 r270 top value=0.1uF
C136 "06033D104KAT2A" 0603 3299.75,3045.39 r180 top value=0.1uF
C137 "06033D104KAT2A" 0603 2806,2824 r90 top value=0.1uF
C138 "06033D104KAT2A" 0603 2639,3319 r0 top value=0.1uF
C139 "06033D104KAT2A" 0603 2712.06,3064.02 r0 top value=0.1uF
D1 "LTST-C190KGKT" LED_LTST-C190_G 1931.85,2244.72 r180 top value=Green
D4 "D_SCHOT_SL03" DO-219AB 1117,1978 r90 top value=SL03
D6 "LTST-C190KGKT" LED_LTST-C190_G 1956.73,3050.16 r180 top value=Green
D7 "NTS245SFT1G" SOD-123FL 1639.73,2960.16 r0 top value=45V
D8 "NTS245SFT1G" SOD-123FL 1863.88,2591.43 r270 top value=45V
D10 "LTST-C190KGKT" LED_LTST-C190_G 1931.73,2454.16 r0 top value=Green
D11 "LTST-C190KGKT" LED_LTST-C190_G 960.6,3341.2 r180 top value=Green
D12 "1N4001RLG" DO-41 1901.12,1083.6 r90 top value=100V
D13 "CMP-0002829-2" LED_LTST-C170_Red 1966,620 r90 top value=Red
D14 "LTST-C190KGKT" LED_LTST-C190_G 1381,2060 r180 top value=Green
D15 "LTST-C190KGKT" LED_LTST-C190_G 1445,1793 r180 top value=Green
FID1 "Fiducial" Fiducial10-30 112,596 r0 top
FID2 "Fiducial" Fiducial10-30 3488,4105 r0 top
FID3 "Fiducial" Fiducial10-30 124,4199 r0 top
H1 "SJ61A1" Bumpon_SJ61A1 2982,3877 r180 bottom
H2 "SJ61A1" Bumpon_SJ61A1 2982,2476 r180 bottom
H3 "SJ61A1" Bumpon_SJ61A1 1955,3271 r180 bottom
H4 "SJ61A1" Bumpon_SJ61A1 656,3877 r180 bottom
H5 "SJ61A1" Bumpon_SJ61A1 656,2476 r180 bottom
H6 "SJ61A1" Bumpon_SJ61A1 155,591 r180 bottom
H7 "SJ61A1" Bumpon_SJ61A1 155,1932 r180 bottom
H8 "SJ61A1" Bumpon_SJ61A1 2110,1323 r180 bottom
H9 "SJ61A1" Bumpon_SJ61A1 2924,1858 r180 bottom
H10 "SJ61A1" Bumpon_SJ61A1 2947,465 r180 bottom
J1 "1751248" CONN_1751248 139.99,3530.25 r270 top
J3 "61300411021" Wurth_61300411021 1460.98,4168.71 r180 top
J4 "1751248" CONN_1751248 139.88,2641.06 r270 top
J6 "1751248" CONN_1751248 2345.75,2309.72 r0 top
J7 "PBC02SAAN" Sullins_PBC02SAAN 688,1249 r90 top
J8 "PBC02SAAN" Sullins_PBC02SAAN 1753.88,3074.43 r90 top
J9 "PBC02SAAN" Sullins_PBC02SAAN 1240,1265 r180 top
J10 "PBC02SAAN" Sullins_PBC02SAAN 1187,1026 r90 top
J11 "1751248" CONN_1751248 135.86,1125.68 r270 top
J12 "PBC02SAAN" Sullins_PBC02SAAN 1621,2459 r0 top
J13 "PEC05DAAN" CONN_PEC05DAAN 1215.84,658.96 r0 top
J14 "1751248" CONN_1751248 3474.86,1772.78 r90 top
J15 "PBC02SAAN" Sullins_PBC02SAAN 3065.54,3076.18 r180 top
J16 "PBC02SAAN" Sullins_PBC02SAAN 1118,1264 r0 top
J17 "PBC02SAAN" Sullins_PBC02SAAN 637,1087 r0 top
J18 "PBC02SAAN" Sullins_PBC02SAAN 634,342 r270 top
J19 "1751248" CONN_1751248 135.86,207 r270 top
J20 "1751248" CONN_1751248 918.71,4189.88 r180 top
J21 "1751248" CONN_1751248 1852.88,4184.71 r180 top
L1 "2.2uH" 0603L 664.73,2762.16 r180 top
L2 "7447789147" WE-PD-S 1155.92,3018.53 r0 top value=47uH
L3 "BLM18KG601SN1D" 0603 1528.73,2734.16 r180 top value="600 ohm"
L4 "74404024100" WE_LQS_252012 1645.73,2835.16 r90 top value=10uH
L5 "74404024100" WE_LQS_252012 1755.73,2624.16 r270 top value=10uH
L7 "7447714220" WE-PD_1050 2240,1684 r90 top value=22uH
L8 "74408943150" WE-SPC_4838 1308.07,214.98 r0 top value=15uH
Logo1 "WEEE logo" WEEE_Minimum 1667.87,616.73 r0 top
Logo2 "Pb-Free Symbol" Pb-Free_Overlay_Small 1447,1404 r0 top
Logo3 "FCC disclaimer" FCC_disclaimer_stacked 1542.39,-736.58 r0 top
Logo4 "ESD Susceptible" ESD_Overlay_Medium 146.68,3207 r0 top
PT1 "B59830C0160A070" POLYSWITCH_RXE135 393.58,2665.16 r270 top
PT2 "B59830C0160A070" POLYSWITCH_RXE135 3244.86,2012.68 r180 top
Q1 "CSD18531Q5A" DQJ0008A 3120.04,1238 r0 top value=60V
Q2 "2N7002" SOT-23 1376.1,1671.58 r90 top value=60V
Q3 "2N7002" SOT-23 1239,1612 r270 top value=60V
R1 "CRCW06031K21FKEA" 0603S 2057.85,2244.72 r180 top value=1.21k
R2 "CRCW06031R00FKEA" 0603S 662.73,2716.16 r180 top value=1.00
R3 "CRCW0603113KFKEA" 0603S 736.73,2719.16 r270 top value=113k
R4 "CRCW060316K9FKEA" 0603S 754.73,2912.16 r180 top value=16.9k
R5 "RT0603FRE07100KL" 0603 1102.47,2779.94 r270 top value=100k
R6 "RC0603FR-07100KL" 0603 1133.72,1576 r270 top value=100k
R7 "RC0603FR-073KL" 0603 1046.32,2546.43 r270 top value=3.00k
R8 "RC1206FR-071RL" 1206 1354.88,2559.12 r90 top value=1.00
R9 "RC1206FR-071RL" 1206 1227.88,2558.39 r90 top value=1.00
R10 "CRCW06032K00FKEA" 0603S 754.73,2965.16 r0 top value=2.00k
R11 "RC0603FR-071K96L" 0603 981.88,2546.43 r90 top value=1.96k
R14 "CRCW06035K36FKEA" 0603S 2056.73,3050.16 r180 top value=5.36k
R15 "CRCW0603976KFKEA" 0603S 1931.73,2949.16 r90 top value=976k
R16 "CRCW060386K6FKEA" 0603S 1878.73,2949.16 r270 top value=86.6k
R17 "CRCW0603105KFKEA" 0603S 1947.73,2774.16 r0 top value=105k
R18 "CRCW06031M30FKEA" 0603S 2013.73,2602.16 r90 top value=1.30Meg
R19 "CRCW12060000Z0EA" 1206 3125.27,3458.82 r180 top value=0
R20 "CRCW0603100RFKEA" 0603S 1647.73,2645.16 r90 top value=100
R21 "CRCW06035K36FKEA" 0603S 2057.73,2454.16 r0 top value=5.36k
R22 "CRCW06031R00FKEA" 0603S 2056.88,2980.43 r0 top value=1.00
R23 "CRCW06031R00FKEA" 0603S 2020.73,2529.16 r0 top value=1.00
R24 "CRCW06030000Z0EA" 0603 3099.2,4136.98 r180 top value=0
R25 "CRCW06030000Z0EA" 0603 2217.4,4039 r90 top value=0
R26 "CRCW06030000Z0EA" 0603 2247.4,3498.85 r90 top value=0
R27 "CRCW0603249KFKEA" 0603 3099.2,3976.98 r0 top value=249k
R28 "CRCW0603249KFKEA" 0603 2337.4,3844 r180 top value=249k
R29 "CRCW060310K0FKEA" 0603 2984.2,3686.98 r90 top value=10k
R30 "CRCW0603249KFKEA" 0603 3364.2,3791.98 r270 top value=249k
R31 "CRCW06030000Z0EA" 0603 3230.7,4026.98 r180 top value=0
R32 "CRCW060375K0FKEA" 0603 3034.2,3901.98 r180 top value=75.0k
R33 "CRCW06030000Z0EA" 0603 2655.4,3499 r90 top value=0
R34 "CRCW0603249KFKEA" 0603 2532.4,3843.93 r0 top value=249k
R35 "RC0603FR-0727KL" 0603 2337.4,3999 r0 top value=27.0k
R36 "CRCW06030000Z0EA" 0603 3330.7,3991.98 r270 top value=0
R37 "CRCW060375K0FKEA" 0603 3394.2,3886.98 r180 top value=75.0k
R38 "CRCW06030000Z0EA" 0603 2362.4,3499 r90 top value=0
R39 "RC0603FR-0724KL" 0603 2468.9,3999 r0 top value=24.0k
R40 "CRCW06030000Z0EA" 0603 3435.7,3625.49 r270 top value=0
R41 "CRCW06030000Z0EA" 0603 2647.4,4034 r90 top value=0
R42 "CRCW06030000Z0EA" 0603 2916.81,2590.23 r0 top value=0
R43 "CRCW06030000Z0EA" 0603 3013.94,2624.19 r270 top value=0
R44 "CRCW0603100RFKEA" 0603 3385.85,2343.72 r270 top value=100
R45 "CRCW0603100RFKEA" 0603 3193.81,2590.23 r0 top value=100
R46 "CRCW06032K55FKEA" 0603 3468.85,2749.72 r270 top value=2.55k
R47 "CRCW0603100RFKEA" 0603 3395.81,2504.74 r270 top value=100
R48 "CRCW06030000Z0EA" 0603 2948.81,2493.23 r90 top value=0
R49 "CRCW06030000Z0EA" 0603 3012.81,2493.23 r270 top value=0
R50 "CRCW0603100RFKEA" 0603 3400,3264 r90 top value=100
R51 "RC1206JR-070RL" 1206 2083.16,3229.92 r270 top value=0
R52 "CRCW06031R00FKEA" 0603S 437.99,3693.25 r180 top value=1.00
R53 "CRCW060349K9FKEA" 0603 859.77,1247.09 r180 top value=49.9k
R54 "CRCW0603887KFKEA" 0603 449.29,860.16 r90 top value=887k
R55 "CRCW060310K0FKEA" 0603 2630,1662 r0 top value=10.0k
R56 "CRCW060329K4FKEA" 0603 545.84,828.29 r180 top value=29.4k
R57 "RC0603FR-07300RL" 0603 2752.73,1819.43 r270 top value=300
R58 "CRCW060334K0FKEA" 0603 545.84,752.11 r180 top value=34.0k
R59 "CRCW06037K50FKEA" 0603 1015.84,828.96 r270 top value=7.50k
R60 "CRCW060313K3FKEA" 0603 1115.84,828.96 r270 top value=13.3k
R61 "CRCW060326K7FKEA" 0603 1215.84,828.96 r270 top value=26.7k
R62 "CRCW060344K2FKEA" 0603 1315.84,828.96 r270 top value=44.2k
R63 "CRCW0603267KFKEA" 0603 1415.84,828.96 r270 top value=267k
R64 "RC0603FR-0793K1L" 0603 1599.43,1765.99 r180 top value=93.1k
R65 "ERJ-6ENF6812V" 0805_HV 2913.86,943.68 r180 top value=68.1k
R66 "RT0805BRD075K62L" 0805_HV 2915.86,672.68 r180 top value=5.62k
R67 "RC0603FR-07150KL" 0603 1866.43,1901.99 r0 top value=150k
R68 "CRCW060310K0FKEA" 0603 1599.43,1891.99 r180 top value=10.0k
R69 "ERJ-6ENF1182V" 0805_HV 2913.86,857.68 r0 top value=11.8k
R70 "ERJ-6ENF1071V" 0805_HV 2915,494 r0 top value=1.07k
R71 "MCU08050C1003FP500" 0805_HV 2914.12,1031.31 r180 top value=100k
R72 "RC0603FR-0739KL" 0603 1965.12,1901.89 r90 top value=39.0k
R73 "RC0603FR-0763K4L" 0603 1599.43,1828.99 r0 top value=63.4k
R74 "RC0603FR-0737K4L" 0603 1737.43,1902.99 r0 top value=37.4k
R75 "ERJ-3EKF1001V" 0603 1084.18,3341.2 r180 top value=1.00k
R76 "ERJ-3GEY0R00V" 0603 2578.73,1391.43 r0 top value=0
R77 "CSR1206FKR330" 1206 2604.73,1579.43 r180 top value=0.33
R78 "CSR1206FKR330" 1206 2604.73,1474.43 r180 top value=0.33
R79 "CMP-0021998-2" 0603 2327.68,671.64 r180 top value=10.0k
R80 "CMP-0022456-2" 0603 2359.68,569.64 r180 top value=4.75k
R81 "RC0603FR-071K37L" 0603 2357.68,768.64 r270 top value=1.37k
R82 "RC0603FR-0716K5L" 0603 2066.54,1280.89 r90 top value=16.5k
R83 "CRCW060310R0FKEAHP" 0603 2496.68,633.64 r0 top value=10.0
R84 "RT0603DRD076K98L" 0603 2129.54,1280.89 r270 top value="6.98 K"
R85 "ERJ-3EKF1001V" 0603 1889,610 r90 top value=1.00k
R86 "RC0603FR-0710KL" 0603 2424.25,2895 r90 top value=10.0k
R87 "RC0603FR-0710KL" 0603 2821,3124.2 r270 top value=10.0k
R88 "CRCW0603102KFKEA" 0603 295,1907 r90 top value=102k
R89 "CRCW060321K5FKEA" 0603 231.11,1906 r270 top value=21.5k
R90 "CRCW060321K5FKEA" 0603 168,1906 r270 top value=21.5k
R91 "CRCW0603102KFKEA" 0603 919.09,1908.98 r90 top value=102k
R92 "CRCW060321K5FKEA" 0603 855.2,1908.98 r270 top value=21.5k
R93 "CRCW060321K5FKEA" 0603 792.09,1908.98 r270 top value=21.5k
R94 "RC0603FR-0710KL" 0603 2929.54,3012.18 r0 top value=10.0k
R95 "CRCW08050000Z0EA" 0805_HV 3085,1402 r180 top value=0
R96 "CRCW06030000Z0EA" 0603 545.42,891.61 r0 top value=0
R97 "RC0603FR-0747KL" 0603 436,1680 r0 top value=47.0k
R98 "RC0603FR-0747KL" 0603 1070,1577 r90 top value=47.0k
R99 "ERJ-3EKF1001V" 0603 1473,2028 r90 top value=1.00k
R100 "ERJ-3EKF1001V" 0603 1474,1881 r270 top value=1.00k
R101 "RC0603FR-07100KL" 0603 1369.58,1552.92 r0 top value=100k
R102 "RC0603FR-07100KL" 0603 1360,1854 r0 top value=100k
R103 "ERJ-3GEY0R00V" 0603 713.81,3535.25 r0 top value=0
R104 "ERJ-3GEY0R00V" 0603 867.81,3646.25 r90 top value=0
R105 "CRCW0603402KFKEA" 0603 552.5,251 r180 top value=402k
R106 "CRCW060349R9FKEA" 0603 872.07,361.98 r0 top value=49.9
R107 "CRCW0603133KFKEA" 0603 681.5,251 r180 top value=133k
R108 "CRCW0603102KFKEA" 0603 907.07,266.98 r90 top value=102k
R109 "CRCW060325K5FKEA" 0603 907.07,135.98 r90 top value=25.5k
R110 "ERJ-3GEY0R00V" 0603 2785.58,1658.39 r180 top value=0
R111 "ERJ-3GEY0R00V" 0603 2785,1721 r180 top value=0
R112 "ERJ-6GEY0R00V" 0805_HV 2555,2274 r90 top value=0
R113 "ERJ-6GEY0R00V" 0805_HV 1169.99,3680.25 r0 top value=0
R117 "CRCW0603100RFKEA" 0603 3299.75,2980.39 r180 top value=100
R118 "CRCW06030000Z0EA" 0603 2950.31,2691.49 r270 top value=0
R119 "RC0603FR-0710KL" 0603 2608.06,3097.31 r90 top value=10.0k
S1 "PTS820 J20M SMTR LFS" SW_PTS820 574.59,562.96 r90 top
TP1 "5000" Keystone5000 2250.73,2914.16 r0 top
TP2 "5000" Keystone5000 2251.73,2701.16 r90 top
TP3 "Pogo Pad" PogoPad 2984.2,3571.98 r90 top
TP4 "5002" Keystone5002 3069,2755.72 r0 top
TP5 "5000" Keystone5000 3267.85,2261.72 r90 top
TP6 "5000" Keystone5000 3217.85,2792.72 r180 top
TP7 "5002" Keystone5002 3213,3296 r90 top
TP8 "5002" Keystone5002 2773,1476 r270 top
TP9 "5002" Keystone5002 2795.06,2970.6 r180 top
TP10 "5002" Keystone5002 3068.54,3296 r270 top
TP11 "5000" Keystone5000 2232.12,1998.89 r180 top
TP12 "5002" Keystone5002 1581.43,1977.99 r0 top
TP13 "5002" Keystone5002 1819,1992 r180 top
TP14 "5002" Keystone5002 2165,773 r0 top
TP15 "5000" Keystone5000 2657,533 r270 top
TP16 "5002" Keystone5002 2073,625 r90 top
TP17 "5000" Keystone5000 2499,1267 r270 top
TP18 "5000" Keystone5000 1811,1387 r180 top
TP19 "5000" Keystone5000 2368,1397 r90 top
TP20 "5000" Keystone5000 496,2000.04 r270 top
TP21 "5001" Keystone5001 1232,1883 r270 top
TP22 "5000" Keystone5000 705.75,1999.98 r270 top
TP23 "5000" Keystone5000 430,1571 r270 top
TP24 "5000" Keystone5000 1468.88,2624.43 r90 top value=Red
TP26 "5001" Keystone5001 82,1594 r90 top
TP28 "5002" Keystone5002 385,696 r90 top
TP29 "5000" Keystone5000 2217.39,4220.42 r90 top
TP30 "5002" Keystone5002 385,537 r90 top
TP31 "5000" Keystone5000 2738,4105 r90 top
TP32 "5001" Keystone5001 2431,4105 r90 top
TP33 "5002" Keystone5002 681.81,3421.25 r180 top
TP34 "5000" Keystone5000 1804.07,271.98 r90 top
TP35 "5001" Keystone5001 1802.07,87.98 r90 top
TP36 "5000" Keystone5000 2344.07,273.98 r90 top
TP37 "5001" Keystone5001 2342.07,89.98 r90 top
TP38 "5002" Keystone5002 2516.2,3045 r90 top
TP39 "5001" Keystone5001 1933,2051 r90 top
TP40 "5000" Keystone5000 3347,567 r90 top
TP41 "5001" Keystone5001 3497,496 r90 top
TP42 "5002" Keystone5002 1610.98,4031.71 r270 top
TP43 "5000" Keystone5000 1093,3789.42 r90 top
TP44 "5000" Keystone5000 1371,3705 r90 top
TP45 "5002" Keystone5002 3095.39,2885 r90 top
TP46 "5002" Keystone5002 2572.96,3225 r90 top
TP47 "5002" Keystone5002 2771,3372 r90 top
TP48 "5002" Keystone5002 2910.5,3372 r90 top
TP49 "5000" Keystone5000 2621,2743 r90 top
U1 "LM5160DNTR" DNT0012B 866.73,2781.16 r0 top
U2 "TPS65130RGER" RGE0024B 1797.73,2802.16 r0 top
U3 "LM27762DSST" DSS0012B 3229.36,3826.82 r90 top
U4 "TPS7A3901DSC" DSC0010J 2437.4,3684 r90 top
U5 "REF3025AIDBZR" DBZ0003A_N 2785.81,2637.23 r90 top
U6 "OPA2376AID" D0008A_N 3201.81,2450.23 r180 top
U7 "REF5025AIDGKT" DGK0008A_N 2788.81,2474.23 r0 top
U8 "LM4040AIM3-2.5/NOPB" MF03A_N 3353.85,2755.72 r180 top
U9 "LMT84LPM" LP0003A_straight 3543,3233 r180 top
U10 "TLV70433DBVR" DBV0005A_N 2430.87,2673.7 r90 top
U11 "TVS3300DRVR" DRV0006A 534.88,2579.43 r90 top
U12 "TVS0500DRVR" DRV0006A 535.17,2458.16 r270 top
U14 "TVS0500DRVR" DRV0006A 382.24,3593.61 r90 top
U15 "TVS0500DRVR" DRV0006A 381.99,3473.08 r270 top
U16 "TVS3300DRVR" DRV0006A 374.8,1213 r90 top
U17 "TPS26624DRCR" DRC0010J 765.84,868.96 r0 top
U18 "TPS2115ADRBR" DRB0008B 2636.73,1813.43 r90 top
U19 "TVS3300DRVR" DRV0006A 374.55,1087.82 r270 top
U20 "LM76002RNPR" RNP0030B 1781.43,1673.99 r180 top
U21 "LMZ14202TZ-ADJ/NOPB" NDW0007A 3388.86,848.68 r0 top
U22 "TVS3300DRVR" DRV0006A 3245.59,1873.61 r90 top
U23 "LM74610QDGKRQ1" DGK0008A_N 3137,1563 r270 top
U24 "TPS2400DBVR" DBV0005A_N 1019.18,3445.2 r0 top
U25 "TLV1117-33IDRJR" DRJ0008A 1738.12,1072.6 r90 top
U26 "INA211BQDCKRQ1" DCK0006A_L 2481.68,723.64 r180 top
U27 "TPS73801DCQR" DCQ0006A_N 2180.54,1029.89 r270 top
U28 "LM4040AIM3-2.5/NOPB" MF03A_N 2503.68,530.64 r0 top
U29 "TPS3710DSER" DSE0006A 2210.68,591.64 r90 top
U30 "TPS3839E16DBZR" DBZ0003A_N 2523.25,2883 r270 top
U31 "TPS3828-33DBVR" DBV0005A_N 2923,3128.2 r90 top
U32 "LMZM23600SILR" SIL0010A 271.11,1752.04 r90 top
U34 "TVS1400DRVR" DRV0006A 382.28,1993 r270 top
U35 "LMZM23600SILR" SIL0010A 895.2,1753.98 r90 top
U36 "TVS1400DRVR" DRV0006A 1006.37,1996.6 r270 top
U38 "TVS1400DRVR" DRV0006A 2309,4106.65 r180 top
U39 "TVS1400DRVR" DRV0006A 2554,4106.72 r180 top
U40 "TVS2700DRVR" DRV0006A 1016,1105 r270 top
U41 "TVS0500DRVR" DRV0006A 3244.59,1749.61 r270 top
U42 "SN74LVC2G34DRLR" DRL0006A 1358,1931 r0 top
U43 "TPS22917DBVR" DBV0006A_N 736.81,3640.25 r0 top
U44 "TPS560430XFDBVR" DBV0006A_N 1068.07,270.98 r270 top
U45 "TPS7A0533PDBV" DBV0005A_N 2083.07,160.98 r0 top
U46 "TVS3300DRVR" DRV0006A 374.65,268 r90 top
U47 "TVS3300DRVR" DRV0006A 374.41,142.82 r270 top
U48 "TVS1400DRVR" DRV0006A 1168.26,4068.71 r270 top
U49 "TVS1400DRVR" DRV0006A 1168.57,4188.33 r90 top
U50 "TMP235DCK" DCK0005A_N 3455.22,3026 r0 top
U51 "REF3425IDBVR" DBV0006A_N 2913,2846.31 r270 top
U52 "TPS3840DL29DBVR" DBV0005A_N 2707.36,3189.46 r90 top
ZZ1 "This Assembly Note is for PCB labels only" AssemblyNoteLabel -230.15,5585.72 r0 top
ZZ2 "This Assembly Note will show in the PcbDoc and associated outputs" AssemblyNote -230.15,5476.84 r0 top
ZZ3 "This Assembly Note will show in the PcbDoc and associated outputs" AssemblyNote -230.15,5388.28 r0 top
ZZ4 "This Assembly Note will show in the PcbDoc and associated outputs" AssemblyNote -230.15,5299.72 r0 top

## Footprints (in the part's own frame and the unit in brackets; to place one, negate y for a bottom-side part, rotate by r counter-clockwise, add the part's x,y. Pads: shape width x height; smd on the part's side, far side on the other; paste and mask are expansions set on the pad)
0402 [mm] "0402 from SM-752 data"
  rect 0.8x0.6 smd: 1(-0.6,0) 2(0.6,0)
  silkscreen extent -1.22,-0.52 1.22,0.52, body extent -0.55,-0.3 0.55,0.3, height 0.6
0603 [mm] "0603 from SM-752 data"
  rect 1x0.95 smd: 1(-0.8,0) 2(0.8,0)
  silkscreen extent -1.52,-0.69 1.52,0.69, body extent -0.87,-0.47 0.87,0.47, height 1
0603L [mm] "0603 from SM-752 data"
  rect 0.8x0.85 smd: 1(-0.7,0) 2(0.7,0)
  silkscreen extent -0.07,-0.32 0.07,0.32, body extent -0.87,-0.47 0.87,0.47, height 1
0603S [mil]
  rect 20x35 smd: 1(-30,0) 2(30,0)
  silkscreen extent -10,-17 10,17, body extent -34,-19 34,19, height 39
0805_HV [mil] "0805 with 30mil clearance between pads"
  rect 50x63 smd: 1(-40,0) 2(40,0)
  silkscreen extent -74,-40 74,40, body extent -43,-29 43,29, height 57
1206 [mm] "1206 from SM-752 data"
  rect 1.3x1.85 smd: 1(-1.45,0) 2(1.45,0)
  silkscreen extent -2.4,-1.21 2.4,1.21, body extent -1.7,-0.9 1.7,0.9, height 1.35
1206_180 [mm] "1206_180"
  rect 1.1x1.6 smd: 1(-1.7,0) 2(1.7,0)
  silkscreen extent -0.9,-1 0.9,1, body extent -1.75,-0.95 1.75,0.95, height 1.8
1206_180M [mm] "1206_180"
  rect 1.5x1.95 smd: 1(-1.55,0) 2(1.55,0)
  silkscreen extent -2.76,-1.44 2.76,1.44, body extent -1.75,-0.95 1.75,0.95, height 1.8
1210 [mm] "1210 from SM-752 data"
  rect 1.3x2.7 smd: 1(-1.45,0) 2(1.45,0)
  silkscreen extent -2.32,-1.57 2.32,1.57, body extent -1.7,-1.35 1.7,1.35, height 1.35
1210_270 [mm] "1210"
  rect 1.3x2.7 smd: 1(-1.45,0) 2(1.45,0)
  silkscreen extent -2.32,-1.57 2.32,1.57, body extent -1.7,-1.35 1.7,1.35, height 2.7
1210_280 [mm] "SMD, 2-Leads, Body 3.6x2.8mm, Height 2.8mm"
  rect 1.1x2.2 smd: 1(-1.65,0) 2(1.65,0)
  silkscreen extent -0.84,-1.4 0.84,1.4, body extent -1.8,-1.4 1.8,1.4, height 2.8
AssemblyNote [mil] "Assembly Note"
AssemblyNoteLabel [mil] "Assembly Note for PCB Labels"
Bumpon_SJ61A1 [mil] "3M Cylindrical Bumpon black"
  round 1 on Mech4: 0(0,0)
  silkscreen extent -156,-156 156,156, body extent -156,-156 156,156, height 201
CONN_1751248 [mil] "Phoenix Contact"
  round 70 hole 43.31: 1(-68.9,0) 2(68.9,0)
  silkscreen extent -148,-142 148,146, body extent -148,-142 148,146, height 335
CONN_PEC05DAAN [mm] "SULLINS"
  rect 1.65x1.65 hole 1.016 mask+0: 1(-5.08,-1.27)
  round 1.65 hole 1.016 mask+0: 2(-5.08,1.27) 3(-2.54,-1.27) 4(-2.54,1.27) 5(0,-1.27) 6(0,1.27) 7(2.54,-1.27) 8(2.54,1.27) 9(5.08,-1.27) 10(5.08,1.27)
  silkscreen extent -7.45,-2.6 6.35,2.54, body extent -6.35,-2.54 6.35,2.54, height 8.38
D0008A_N [mm] "SOIC, 8-Leads, Body 4.9x3.9mm, Pitch 1.27mm, IPC Medium Density"
  oval 1.45x0.6 smd: 1(-2.725,1.905) 2(-2.725,0.635) 3(-2.725,-0.635) 4(-2.725,-1.905) 5(2.725,-1.905) 6(2.725,-0.635) 7(2.725,0.635) 8(2.725,1.905)
  silkscreen extent -3.3,-2.5 0.9,2.5, body extent -3,-2.45 3,2.45, height 1.63
DBV0005A_N [mm] "SOT23, 5-Leads, Body 2.9x1.6mm, Pitch 0.95mm, Lead Span 2.8mm, IPC Medium Density"
  rrect17% 1x0.6 smd: 1(-1.375,0.95) 2(-1.375,0) 3(-1.375,-0.95) 4(1.375,-0.95) 5(1.375,0.95)
  silkscreen extent -1.63,-1.55 0.38,1.55, body extent -1.42,-1.46 1.42,1.46, height 1.09
DBV0006A_N [mm] "SOT23, 6-Leads, Body 2.9x1.6mm, Pitch 0.95mm, Lead Span 2.8mm, IPC Medium Density"
  rrect17% 1x0.6 smd: 1(-1.375,0.95) 2(-1.375,0) 3(-1.375,-0.95) 4(1.375,-0.95) 5(1.375,0) 6(1.375,0.95)
  silkscreen extent -1.68,-1.55 0.5,1.55, body extent -1.42,-1.46 1.42,1.46, height 1.12
DBZ0003A_N [mm] "SOT23, 3-Leads, Body 2.9x1.3mm, Pitch 0.95mm, Lead Span 2.4mm, IPC Medium Density"
  rrect17% 1x0.6 smd: 1(-1.2,0.95) 2(-1.2,-0.95) 3(1.2,0)
  silkscreen extent -1.65,-1.5 0.7,1.5, body extent -1.26,-1.46 1.26,1.46, height 0.98
DCK0005A_N [mm] "SOT353, 5-Leads, Body 2x1.3mm, Pitch 0.65mm, Lead Span 2.1mm, IPC Medium Density"
  rrect25% 0.85x0.4 smd: 1(-1.125,0.65) 2(-1.125,0) 3(-1.125,-0.65) 4(1.125,-0.65) 5(1.125,0.65)
  silkscreen extent -0.15,-1.1 0.15,1.1, body extent -1.14,-1 1.14,1, height 0.95
DCK0006A_L [mm] "SOT23, 6-Leads, Body 2x1.3mm, Pitch 0.65mm, Lead Span 2.1mm, IPC High Density"
  rrect25% 0.65x0.4 smd: 1(-1.025,0.65) 2(-1.025,0) 3(-1.025,-0.65) 4(1.025,-0.65) 5(1.025,0) 6(1.025,0.65)
  silkscreen extent -0.25,-1.1 0.25,1.1, body extent -1.14,-1 1.14,1, height 0.95
DCQ0006A_N [mm] "SOT223, 6-Leads, Body 6.6x7.3mm (max), Pitch 1.27mm, IPC Medium Density"
  rrect17% 2.1x0.6 smd: 1(-2.975,2.54) 2(-2.975,1.27) 3(-2.975,0) 4(-2.975,-1.27) 5(-2.975,-2.54)
  rrect5% 2.1x3.2 smd: 6(2.975,0)
  silkscreen extent -1.5,-3.27 1.5,3.27, body extent -3.54,-3.25 3.54,3.25, height 1.8
DGK0008A_N [mm] "TSOP, 8-Leads, Body 3x3mm, Pitch 0.65mm, IPC Medium Density"
  oval 1.35x0.45 smd: 1(-2.225,0.975) 2(-2.225,0.325) 3(-2.225,-0.325) 4(-2.225,-0.975) 5(2.225,-0.975) 6(2.225,-0.325) 7(2.225,0.325) 8(2.225,0.975)
  silkscreen extent -2.75,-1.55 0.95,1.55, body extent -2.45,-1.5 2.45,1.5, height 0.96
DNT0012B [mm] "SON, 12-Leads, Body 4x4mm, Pitch 0.5mm"
  rrect40% 0.6x0.25 smd: 1(-1.9,1.25) 2(-1.9,0.75) 3(-1.9,0.25) 4(-1.9,-0.25) 5(-1.9,-0.75) 6(-1.9,-1.25) 7(1.9,-1.25) 8(1.9,-0.75) 9(1.9,-0.25) 10(1.9,0.25) 11(1.9,0.75) 12(1.9,1.25)
  rrect4% 2.6x3 smd paste-1.3: 13(0,0)
  silkscreen extent -2.2,-2.2 2.2,2.2, body extent -2.05,-2.05 2.05,2.05, height 0.81
DO-41 [mm] "diode"
  rect 1.75x1.75 hole 1.15: 1(-5.08,0)
  round 1.75 hole 1.15: 2(5.08,0)
  silkscreen extent -2.62,-1.37 2.59,1.35, body extent -5.51,-1.36 5.51,1.36, height 2.72
DO-219AB [mil]
  rect 50x58 smd: 1(-61,0) 2(61,0)
DQJ0008A [mm] "SMD, 8-Leads, Body 5.75x4.9mm"
  rrect39% 0.91x0.51 smd paste-0.05 mask-0.05: 1(-2.795,1.905) 2(-2.795,0.635) 3(-2.795,-0.635) 4(-2.795,-1.905) 5(2.795,-1.905) 6(2.795,-0.635) 7(2.795,0.635) 8(2.795,1.905)
  rrect8% 1.58x1.25 on Top Paste: 9(-0.38,-1.45) 9(-0.38,0) 9(-0.38,1.45) 9(1.4,-1.45) 9(1.4,0) 9(1.4,1.45)
  rrect3% 3.48x4.47 on Top Solder: 9(0.55,0)
  rrect2% 4.49x4.57 smd paste-2.5 mask-2.5: 9(1.005,0)
  silkscreen extent -3,-2.6 3,2.6, body extent -3.13,-2.45 3.13,2.45, height 1.15
DRB0008B [mm] "SON, 8-Leads, Body 3x3mm, Pitch 0.65mm, Thermal Pad 2.4x1.65mm, TI Recommended"
  oval 0.6x0.3 smd: 1(-1.4,0.975) 2(-1.4,0.325) 3(-1.4,-0.325) 4(-1.4,-0.975) 5(1.4,-0.975) 6(1.4,-0.325) 7(1.4,0.325) 8(1.4,0.975)
  rect 1.65x2.4 smd paste-1.2: 9(0,0)
  silkscreen extent -1.73,-1.73 1.73,1.73, body extent -1.57,-1.57 1.58,1.58, height 1.01
DRC0010J [mm] "SON, 10-Leads, Body 3x3mm, Pitch 0.5mm, Thermal Pad 2.4x1.65mm, TI Recommended"
  rrect40% 0.6x0.25 smd: 1(-1.4,1) 2(-1.4,0.5) 3(-1.4,0) 4(-1.4,-0.5) 5(-1.4,-1) 6(1.4,-1) 7(1.4,-0.5) 8(1.4,0) 9(1.4,0.5) 10(1.4,1)
  rrect40% 0.25x0.34 on Top Paste: 11(-0.25,-1.53) 11(-0.25,1.53) 11(0.25,-1.53) 11(0.25,1.53)
  rrect9% 1.5x1.06 on Top Paste: 11(0,-0.63) 11(0,0.63)
  rrect12% 1.65x2.4 smd paste-1 mask-2: 11(0,0)
  Top Layer region: -0.775,-1.25 -0.425,-1.25 -0.425,-1.65 -0.417,-1.688 -0.396,-1.721 -0.363,-1.742 -0.325,-1.75 -0.325,-1.75 -0.325,-1.75 -0.175,-1.75 -0.175,-1.75 -0.137,-1.742 -0.104,-1.721 -0.083,-1.688 -0.075,-1.65 -0.075,-1.65 -0.075,-1.25 0.075,-1.25 0.075,-1.65 0.083,-1.688 0.104,-1.721 0.137,-1.742 0.175,-1.75 0.175,-1.75 0.175,-1.75 0.325,-1.75 0.325,-1.75 0.363,-1.742 0.396,-1.721 0.417,-1.688 0.425,-1.65 0.425,-1.65 0.425,-1.25 0.775,-1.25 0.813,-1.242 0.846,-1.221 0.867,-1.188 0.875,-1.15 0.875,-1.15 0.875,1.15 0.867,1.188 0.846,1.221 0.813,1.242 0.775,1.25 0.775,1.25 0.425,1.25 0.425,1.65 0.417,1.688 0.396,1.721 0.363,1.742 0.325,1.75 0.325,1.75 0.175,1.75 0.137,1.742 0.104,1.721 0.083,1.688 0.075,1.65 0.075,1.65 0.075,1.25 -0.075,1.25 -0.075,1.65 -0.083,1.688 -0.104,1.721 -0.137,1.742 -0.175,1.75 -0.175,1.75 -0.325,1.75 -0.363,1.742 -0.396,1.721 -0.417,1.688 -0.425,1.65 -0.425,1.65 -0.425,1.25 -0.775,1.25 -0.813,1.242 -0.846,1.221 -0.867,1.188 -0.875,1.15 -0.875,1.15 -0.875,-1.15 -0.867,-1.188 -0.846,-1.221 -0.813,-1.242 -0.775,-1.25
  silkscreen extent -1.63,-1.63 1.63,1.63, body extent -1.5,-1.5 1.5,1.5, height 0.77
DRJ0008A [mm] "SON, 8-Leads, Body 4x4mm, Pitch 0.8mm, Thermal Pad 3x2.2mm, TI Recommended"
  oval 0.7x0.3 smd: 1(-1.9,1.2) 2(-1.9,0.4) 3(-1.9,-0.4) 4(-1.9,-1.2) 5(1.9,-1.2) 6(1.9,-0.4) 7(1.9,0.4) 8(1.9,1.2)
  rect 2.2x3 smd paste-1.1: 9(0,0)
  silkscreen extent -2.2,-2.2 2.2,2.2, body extent -2.05,-2.05 2.05,2.05, height 0.81
DRL0006A [mm] "SOTFL, 6-Flat Leads, Body 1.2x1.6x0.6mm, Pitch 0.5mm, TI recommended"
  rrect33% 0.67x0.3 smd: 1(-0.74,0.5) 2(-0.74,0) 3(-0.74,-0.5) 4(0.74,-0.5) 5(0.74,0) 6(0.74,0.5)
  silkscreen extent -0.9,-0.95 0.5,0.95, body extent -0.8,-0.8 0.8,0.8, height 0.61
DRV0006A [mm] "SON, 6-Leads, Body 2x2mm, Pitch 0.65mm, Thermal Pad 1.6x1mm, TI Recommended"
  rrect33% 0.45x0.3 smd: 1(-0.975,0.65) 2(-0.975,0) 3(-0.975,-0.65) 4(0.975,-0.65) 5(0.975,0) 6(0.975,0.65)
  rrect14% 1x0.7 on Top Paste: 7(0,0.45) 7(0,-0.45)
  rrect10% 1x1.6 smd paste-0.5: 7(0,0)
  silkscreen extent -1.05,-1.2 1.05,1.2, body extent -1.05,-1.05 1.05,1.05, height 0.81
DSC0010J [mm] "SON, 10-Leads, Body 3x3mm, Pitch 0.5mm, Thermal Pad 2.4x1.65mm, TI Recommended"
  rrect100% 0.6x0.24 smd: 1(-1.4,1) 2(-1.4,0.5) 3(-1.4,0) 4(-1.4,-0.5) 5(-1.4,-1) 6(1.4,-1) 7(1.4,-0.5) 8(1.4,0) 9(1.4,0.5) 10(1.4,1)
  rrect6% 1.65x2.4 smd paste-0.825: 11(0,0)
  silkscreen extent -1.7,-1.7 1.7,1.7, body extent -1.57,-1.57 1.57,1.57, height 0.81
DSE0006A [mm] "TI recommended land pattern"
  rect 0.66x0.25 smd: 1(-0.62,0.5)
  rect 0.7x0.25 smd: 2(-0.6,0) 3(-0.6,-0.5) 4(0.6,-0.5) 5(0.6,0) 6(0.6,0.5)
  Top Layer region: -0.3,0.625 -0.25,0.625 -0.15,0.525 -0.15,0.375 -0.3,0.375
  silkscreen extent -0.9,-0.92 0.9,0.92, body extent -0.77,-0.77 0.77,0.77, height 0.8
DSS0012B [mm] "SON, 12-Leads, Body 2x3mm, Pitch 0.5mm, Thermal Pad 2.65x1.0mm, TI Recommended"
  rrect40% 0.5x0.25 smd: 1(-0.95,1.25) 2(-0.95,0.75) 3(-0.95,0.25) 4(-0.95,-0.25) 5(-0.95,-0.75) 6(-0.95,-1.25) 7(0.95,-1.25) 8(0.95,-0.75) 9(0.95,-0.25) 10(0.95,0.25) 11(0.95,0.75) 12(0.95,1.25)
  rrect11% 0.949x1.168 on Top Paste: 13(0,0.684) 13(0,-0.684)
  rrect11% 1x2.65 smd paste-0.5: 13(0,0)
  silkscreen extent -1.05,-1.7 1.05,1.7, body extent -1,-1.5 1,1.5, height 0.81
ESD_Overlay_Medium [mil]
  silkscreen extent -127,-109 125,110
FCC_disclaimer_stacked [mil]
Fiducial10-30 [mm]
  round 1 smd mask+1: 1(0,0)
  Top Layer keep-out circle w1.678: c0,0 r0.75
Keystone5000 [mil] "For Keystone 500x miniature loop terminals"
  round 80 hole 40: 1(0,0)
  silkscreen extent -52,-52 52,52, body extent -49,-49 49,49, height 182
Keystone5001 [mil] "For Keystone 500x miniature loop terminals"
  round 80 hole 40: 1(0,0)
  silkscreen extent -52,-52 52,52, body extent -49,-49 49,49, height 182
Keystone5002 [mil] "For Keystone 500x miniature loop terminals"
  round 80 hole 40: 1(0,0)
  silkscreen extent -52,-52 52,52, body extent -49,-49 49,49, height 182
LED_LTST-C170_Red [mm] "LITE-ON"
  rect 1.2x1.2 smd: 1(-1.05,0) 2(1.05,0)
  silkscreen extent -1.6,-1 2.2,1, body extent -1.05,-0.67 1.05,0.67, height 1.1
LED_LTST-C190_G [mm] "Lite-On"
  rect 0.8x0.8 smd: 1(-0.75,0) 2(0.75,0)
  silkscreen extent 1.37,-0.5 1.75,0.5, body extent -0.85,-0.45 0.85,0.45, height 0.9
LP0003A_straight [mm] "TH, 3-Leads, Pin Spacing 1.27mm"
  rrect9% 1.5x1.07 hole 0.85: 1(0,1.27)
  rrect100% 1.5x1.07 hole 0.85: 2(0,0) 3(0,-1.27)
  silkscreen extent -1.33,-2.41 2.65,2.42, body extent -1.34,-2.41 2.35,2.41, height 6.84
MF03A_N [mm] "SOT23, 3-Leads, Body 2.9x1.3mm, Pitch 0.95mm, Lead Span 2.4mm, IPC Medium Density"
  rect 1.3x0.6 smd: 1(-1.05,0.95) 2(-1.05,-0.95) 3(1.05,0)
  silkscreen extent -1.18,-1.5 0.7,1.92, body extent -0.7,-1.5 0.7,1.5, height 1.12
NDW0007A [mm] "TI Recommended"
  rect 3.06x0.89 smd: 1(-7.305,3.81) 2(-7.305,2.54) 3(-7.305,1.27) 4(-7.305,0) 5(-7.305,-1.27) 6(-7.305,-2.54) 7(-7.305,-3.81)
  rect 8.54x5.35 smd: 8(0,0)
  silkscreen extent -6.65,-5.09 5.27,5.1, body extent -8.49,-5.08 5.27,5.08, height 4.78
Pb-Free_Overlay_Small [mil]
  silkscreen extent -46,-46 46,46
PogoPad [mil] "No Solder Paste"
  round 70 smd paste-35: 1(0,0)
POLYSWITCH_RXE135 [mil]
  round 85 hole 47: 1(-100,0) 2(100,0)
  silkscreen extent -335,-75 335,75
RGE0024B [mm] "QFN, 24-Leads, Body 4x4mm, Pitch 0.5mm, Thermal Pad 2.45x2.45mm, TI Recommended"
  oval 0.6x0.24 smd: 1(-1.9,1.25) 2(-1.9,0.75) 3(-1.9,0.25) 4(-1.9,-0.25) 5(-1.9,-0.75) 6(-1.9,-1.25) 13(1.9,-1.25) 14(1.9,-0.75) 15(1.9,-0.25) 16(1.9,0.25) 17(1.9,0.75) 18(1.9,1.25)
  oval 0.24x0.6 smd: 7(-1.25,-1.9) 8(-0.75,-1.9) 9(-0.25,-1.9) 10(0.25,-1.9) 11(0.75,-1.9) 12(1.25,-1.9) 19(1.25,1.9) 20(0.75,1.9) 21(0.25,1.9) 22(-0.25,1.9) 23(-0.75,1.9) 24(-1.25,1.9)
  rect 2.45x2.45 smd paste-1.225: 25(0,0)
  silkscreen extent -2.23,-2.22 2.22,2.23, body extent -2.07,-2.07 2.07,2.07, height 1.01
RNP0030B [mm] "QFN, 30-Leads, Body 6x4mm, Pitch 0.5mm, Thermal Pad 1.8x4.5mm"
  rrect40% 0.75x0.25 smd: 1(-1.825,2.5) 2(-1.825,2) 3(-1.825,1.5) 4(-1.825,1) 5(-1.825,0.5) 6(-1.825,0) 7(-1.825,-0.5) 8(-1.825,-1) 9(-1.825,-1.5) 10(-1.825,-2) 11(-1.825,-2.5) 16(1.825,-2.5) 17(1.825,-2) 18(1.825,-1.5) 19(1.825,-1) 20(1.825,-0.5) 21(1.825,0) 22(1.825,0.5) 23(1.825,1) 24(1.825,1.5) 25(1.825,2) 26(1.825,2.5)
  rrect40% 0.25x0.6 smd: 12(-0.75,-2.9) 13(-0.25,-2.9) 14(0.25,-2.9) 15(0.75,-2.9) 27(0.75,2.9) 28(0.25,2.9) 29(-0.25,2.9) 30(-0.75,2.9)
  rrect12% 0.8x0.94 on Top Paste: 31(-0.5,1.71) 31(-0.5,0.57) 31(-0.5,-0.57) 31(-0.5,-1.71) 31(0.5,1.71) 31(0.5,0.57) 31(0.5,-0.57) 31(0.5,-1.71)
  rrect5% 1.8x4.5 smd paste-3: 31(0,0)
  silkscreen extent -2.17,-3.18 2.17,3.18, body extent -2,-3 2,3, height 0.8
SIL0010A [mm] "MicoSiP, TI recommended land pattern"
  rrect50% 0.75x0.4 smd paste-0.05 mask-0.05: 1(-1.525,1.2) 2(-1.525,0.6) 3(-1.525,0) 4(-1.525,-0.6) 5(-1.525,-1.2) 6(1.525,-1.2) 7(1.525,-0.6) 8(1.525,0) 9(1.525,0.6) 10(1.525,1.2)
  rrect14% 0.7x0.833 on Top Paste: 11(-0.175,1.03) 11(-0.175,0) 11(-0.175,-1.03)
  rrect25% 0.8x3 smd paste-0.5 mask-0.05: 11(-0.175,0)
  silkscreen extent 1.7,1.68 1.9,1.68, body extent -1.9,-1.5 1.9,1.5, height 1.49
SOD-123FL [mm] "Copied from SOD-123"
  rect 0.915x1.22 smd: 1(-1.637,0) 2(1.637,0)
  silkscreen extent -2.74,-1.16 1.68,1.16, body extent -1.9,-0.9 1.9,0.9, height 1
SOT-23 [mm] "SOT23, 3-Leads, Body 2.9x1.3mm, Pitch 0.95mm, Lead Span 2.5mm, IPC Medium Density"
  rrect50% 1x0.6 smd: 1(-1.2,0.95) 2(-1.2,-0.95) 3(1.2,0)
  silkscreen extent -1.62,-1.5 0.7,1.5, body extent -1.16,-1.45 1.21,1.45, height 1
Sullins_PBC02SAAN [mm] "Sullins 100mil, 1x2, 230 mil above insulator"
  rect 1.65x1.65 hole 1.016: 1(0,1.27)
  round 1.65 hole 1.016: 2(0,-1.27)
  silkscreen extent -1.37,-2.54 1.27,3.1, body extent -1.27,-2.54 1.27,2.54, height 8.38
